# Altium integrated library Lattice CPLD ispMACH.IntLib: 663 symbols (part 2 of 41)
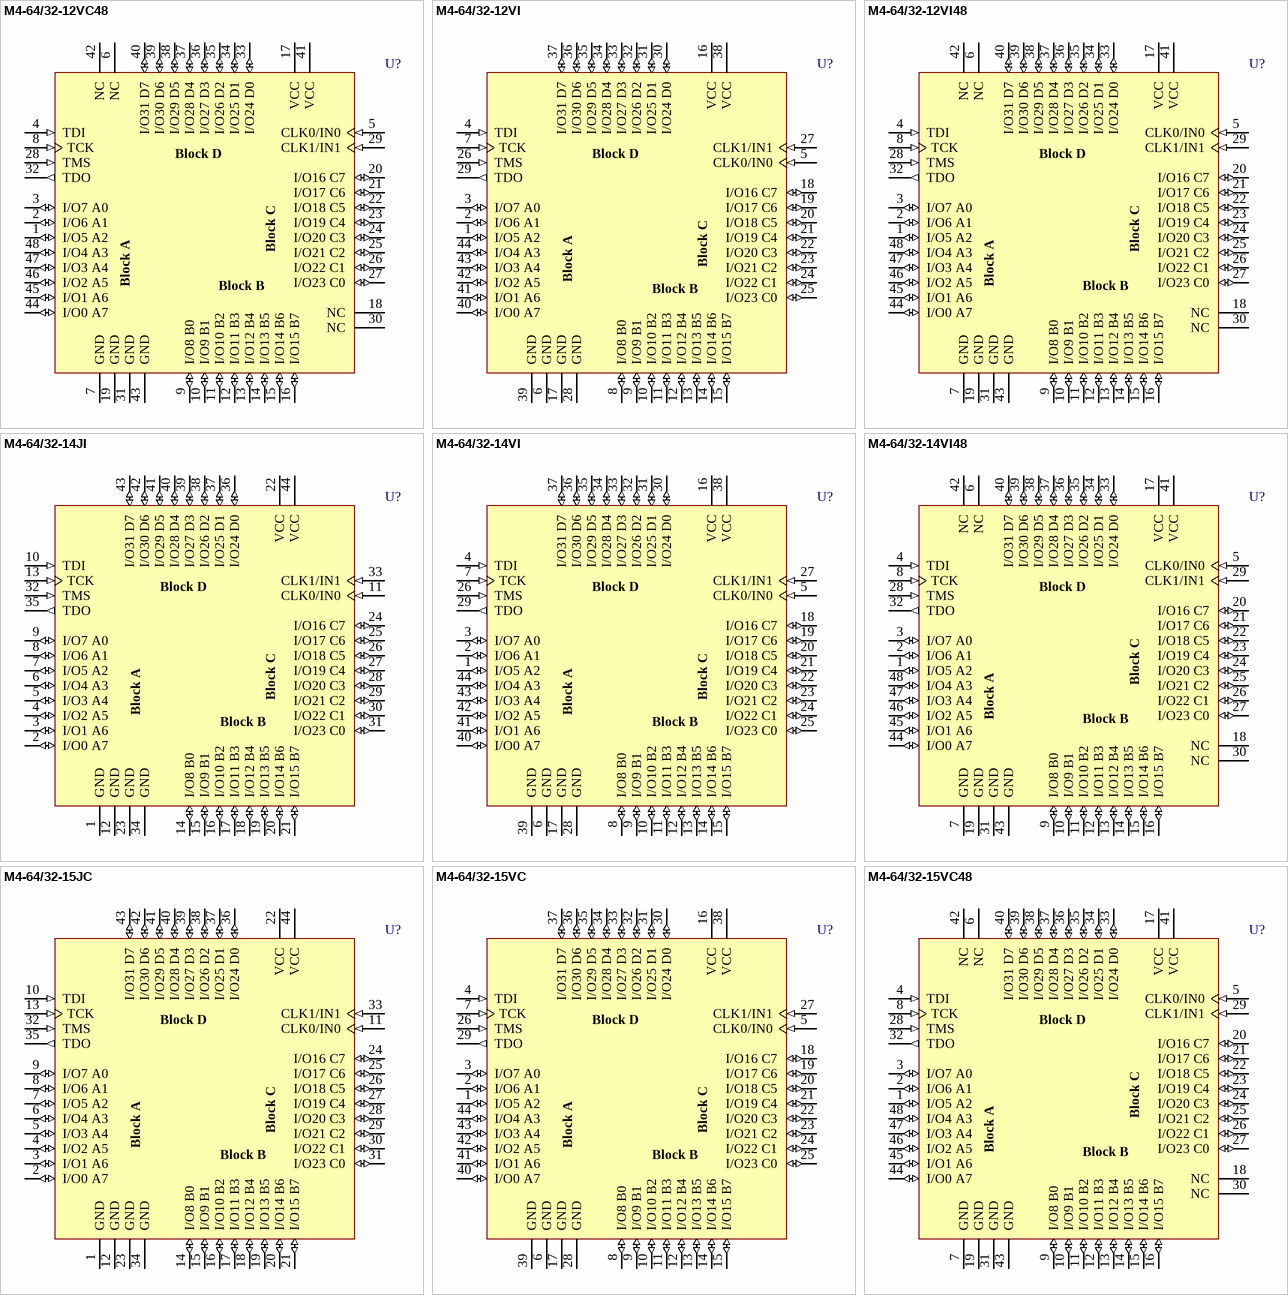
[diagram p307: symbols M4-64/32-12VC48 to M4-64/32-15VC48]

## M4-64/32-14VI48
designator U?
High-Performance EE CMOS In-System Programmable Logic
footprint TQFP48_N (Thin QFP, 48-Leads, Body 7x7mm, Pitch 0.5mm, IPC Medium Density)
footprint TQFP48_L (Thin QFP, 48-Leads, Body 7x7mm, Pitch 0.5mm, IPC High Density)
footprint TQFP48_M (Thin QFP, 48-Leads, Body 7x7mm, Pitch 0.5mm, IPC Low Density)
3D model M4-TQFP48 (48-Pin Thin Quad Flat Pack 0.5 mm Pitch)
pins: 1 I/O5 A2 (io), 2 I/O6 A1 (io), 3 I/O7 A0 (io), 4 TDI (in), 5 CLK0/IN0 (in), 6 NC, 7 GND (power), 8 TCK (in), 9 I/O8 B0 (io), 10 I/O9 B1 (io), 11 I/O10 B2 (io), 12 I/O11 B3 (io), 13 I/O12 B4 (io), 14 I/O13 B5 (io), 15 I/O14 B6 (io), 16 I/O15 B7 (io), 17 VCC (power), 18 NC, 19 GND (power), 20 I/O16 C7 (io), 21 I/O17 C6 (io), 22 I/O18 C5 (io), 23 I/O19 C4 (io), 24 I/O20 C3 (io), 25 I/O21 C2 (io), 26 I/O22 C1 (io), 27 I/O23 C0 (io), 28 TMS (in), 29 CLK1/IN1 (in), 30 NC, 31 GND (power), 32 TDO (out), 33 I/O24 D0 (io), 34 I/O25 D1 (io), 35 I/O26 D2 (io), 36 I/O27 D3 (io), 37 I/O28 D4 (io), 38 I/O29 D5 (io), 39 I/O30 D6 (io), 40 I/O31 D7 (io), 41 VCC (power), 42 NC, 43 GND (power), 44 I/O0 A7 (io), 45 I/O1 A6 (io), 46 I/O2 A5 (io), 47 I/O3 A4 (io), 48 I/O4 A3 (io)

## M4-64/32-15JC
designator U?
High-Performance EE CMOS In-System Programmable Logic
footprint PLCC44_N (Leaded Chip Carrier, 44-Leads, Body 16.6x16.6mm, Pitch 1.27mm, IPC Medium Density)
footprint PLCC44_L (Leaded Chip Carrier, 44-Leads, Body 16.6x16.6mm, Pitch 1.27mm, IPC High Density)
footprint PLCC44_M (Leaded Chip Carrier, 44-Leads, Body 16.6x16.6mm, Pitch 1.27mm, IPC Low Density)
3D model M4-PLCC44 (44-Pin Leaded Chip Carrier 1.27 mm Pitch)
pins: 1 GND (power), 2 I/O0 A7 (io), 3 I/O1 A6 (io), 4 I/O2 A5 (io), 5 I/O3 A4 (io), 6 I/O4 A3 (io), 7 I/O5 A2 (io), 8 I/O6 A1 (io), 9 I/O7 A0 (io), 10 TDI (in), 11 CLK0/IN0 (in), 12 GND (power), 13 TCK (in), 14 I/O8 B0 (io), 15 I/O9 B1 (io), 16 I/O10 B2 (io), 17 I/O11 B3 (io), 18 I/O12 B4 (io), 19 I/O13 B5 (io), 20 I/O14 B6 (io), 21 I/O15 B7 (io), 22 VCC (power), 23 GND (power), 24 I/O16 C7 (io), 25 I/O17 C6 (io), 26 I/O18 C5 (io), 27 I/O19 C4 (io), 28 I/O20 C3 (io), 29 I/O21 C2 (io), 30 I/O22 C1 (io), 31 I/O23 C0 (io), 32 TMS (in), 33 CLK1/IN1 (in), 34 GND (power), 35 TDO (out), 36 I/O24 D0 (io), 37 I/O25 D1 (io), 38 I/O26 D2 (io), 39 I/O27 D3 (io), 40 I/O28 D4 (io), 41 I/O29 D5 (io), 42 I/O30 D6 (io), 43 I/O31 D7 (io), 44 VCC (power)

## M4-64/32-15VC
designator U?
High-Performance EE CMOS In-System Programmable Logic
footprint TQFP44_N (Thin QFP, 44-Leads, Body 10x10mm, Pitch 0.8mm, IPC Medium Density)
footprint TQFP44_L (Thin QFP, 44-Leads, Body 10x10mm, Pitch 0.8mm, IPC High Density)
footprint TQFP44_M (Thin QFP, 44-Leads, Body 10x10mm, Pitch 0.8mm, IPC Low Density)
3D model M4-TQFP44 (44-Pin Thin Quad Flat Pack 0.8 mm Pitch)
pins: 1 I/O5 A2 (io), 2 I/O6 A1 (io), 3 I/O7 A0 (io), 4 TDI (in), 5 CLK0/IN0 (in), 6 GND (power), 7 TCK (in), 8 I/O8 B0 (io), 9 I/O9 B1 (io), 10 I/O10 B2 (io), 11 I/O11 B3 (io), 12 I/O12 B4 (io), 13 I/O13 B5 (io), 14 I/O14 B6 (io), 15 I/O15 B7 (io), 16 VCC (power), 17 GND (power), 18 I/O16 C7 (io), 19 I/O17 C6 (io), 20 I/O18 C5 (io), 21 I/O19 C4 (io), 22 I/O20 C3 (io), 23 I/O21 C2 (io), 24 I/O22 C1 (io), 25 I/O23 C0 (io), 26 TMS (in), 27 CLK1/IN1 (in), 28 GND (power), 29 TDO (out), 30 I/O24 D0 (io), 31 I/O25 D1 (io), 32 I/O26 D2 (io), 33 I/O27 D3 (io), 34 I/O28 D4 (io), 35 I/O29 D5 (io), 36 I/O30 D6 (io), 37 I/O31 D7 (io), 38 VCC (power), 39 GND (power), 40 I/O0 A7 (io), 41 I/O1 A6 (io), 42 I/O2 A5 (io), 43 I/O3 A4 (io), 44 I/O4 A3 (io)

## M4-64/32-15VC48
designator U?
High-Performance EE CMOS In-System Programmable Logic
footprint TQFP48_N (Thin QFP, 48-Leads, Body 7x7mm, Pitch 0.5mm, IPC Medium Density)
footprint TQFP48_L (Thin QFP, 48-Leads, Body 7x7mm, Pitch 0.5mm, IPC High Density)
footprint TQFP48_M (Thin QFP, 48-Leads, Body 7x7mm, Pitch 0.5mm, IPC Low Density)
3D model M4-TQFP48 (48-Pin Thin Quad Flat Pack 0.5 mm Pitch)
pins: 1 I/O5 A2 (io), 2 I/O6 A1 (io), 3 I/O7 A0 (io), 4 TDI (in), 5 CLK0/IN0 (in), 6 NC, 7 GND (power), 8 TCK (in), 9 I/O8 B0 (io), 10 I/O9 B1 (io), 11 I/O10 B2 (io), 12 I/O11 B3 (io), 13 I/O12 B4 (io), 14 I/O13 B5 (io), 15 I/O14 B6 (io), 16 I/O15 B7 (io), 17 VCC (power), 18 NC, 19 GND (power), 20 I/O16 C7 (io), 21 I/O17 C6 (io), 22 I/O18 C5 (io), 23 I/O19 C4 (io), 24 I/O20 C3 (io), 25 I/O21 C2 (io), 26 I/O22 C1 (io), 27 I/O23 C0 (io), 28 TMS (in), 29 CLK1/IN1 (in), 30 NC, 31 GND (power), 32 TDO (out), 33 I/O24 D0 (io), 34 I/O25 D1 (io), 35 I/O26 D2 (io), 36 I/O27 D3 (io), 37 I/O28 D4 (io), 38 I/O29 D5 (io), 39 I/O30 D6 (io), 40 I/O31 D7 (io), 41 VCC (power), 42 NC, 43 GND (power), 44 I/O0 A7 (io), 45 I/O1 A6 (io), 46 I/O2 A5 (io), 47 I/O3 A4 (io), 48 I/O4 A3 (io)

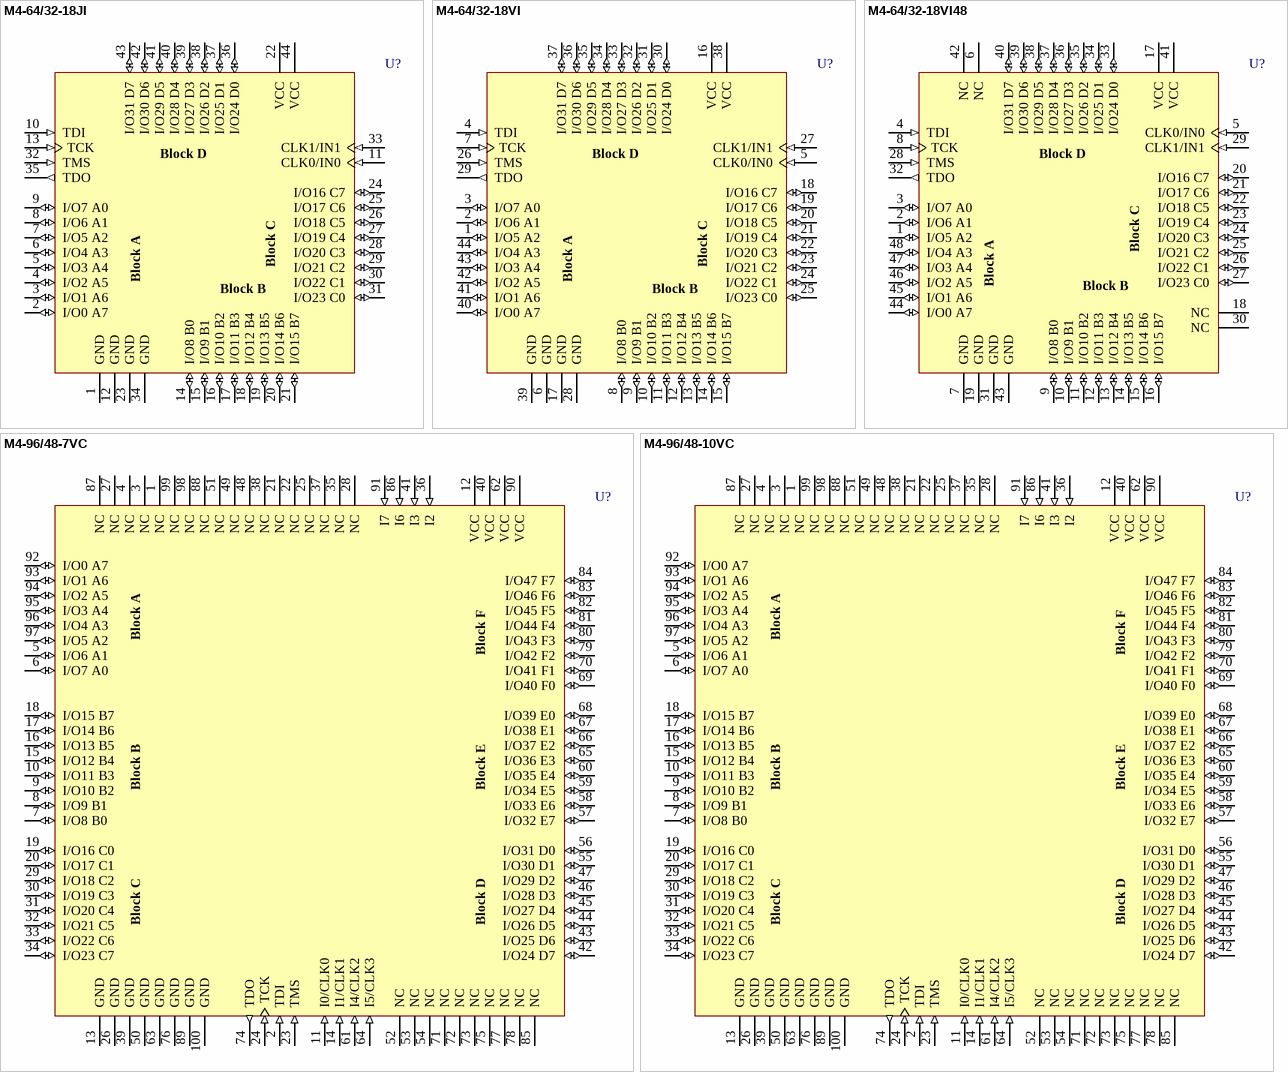
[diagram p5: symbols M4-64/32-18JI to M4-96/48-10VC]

## M4-64/32-18JI
designator U?
High-Performance EE CMOS In-System Programmable Logic
footprint PLCC44_N (Leaded Chip Carrier, 44-Leads, Body 16.6x16.6mm, Pitch 1.27mm, IPC Medium Density)
footprint PLCC44_L (Leaded Chip Carrier, 44-Leads, Body 16.6x16.6mm, Pitch 1.27mm, IPC High Density)
footprint PLCC44_M (Leaded Chip Carrier, 44-Leads, Body 16.6x16.6mm, Pitch 1.27mm, IPC Low Density)
3D model M4-PLCC44 (44-Pin Leaded Chip Carrier 1.27 mm Pitch)
pins: 1 GND (power), 2 I/O0 A7 (io), 3 I/O1 A6 (io), 4 I/O2 A5 (io), 5 I/O3 A4 (io), 6 I/O4 A3 (io), 7 I/O5 A2 (io), 8 I/O6 A1 (io), 9 I/O7 A0 (io), 10 TDI (in), 11 CLK0/IN0 (in), 12 GND (power), 13 TCK (in), 14 I/O8 B0 (io), 15 I/O9 B1 (io), 16 I/O10 B2 (io), 17 I/O11 B3 (io), 18 I/O12 B4 (io), 19 I/O13 B5 (io), 20 I/O14 B6 (io), 21 I/O15 B7 (io), 22 VCC (power), 23 GND (power), 24 I/O16 C7 (io), 25 I/O17 C6 (io), 26 I/O18 C5 (io), 27 I/O19 C4 (io), 28 I/O20 C3 (io), 29 I/O21 C2 (io), 30 I/O22 C1 (io), 31 I/O23 C0 (io), 32 TMS (in), 33 CLK1/IN1 (in), 34 GND (power), 35 TDO (out), 36 I/O24 D0 (io), 37 I/O25 D1 (io), 38 I/O26 D2 (io), 39 I/O27 D3 (io), 40 I/O28 D4 (io), 41 I/O29 D5 (io), 42 I/O30 D6 (io), 43 I/O31 D7 (io), 44 VCC (power)

## M4-64/32-18VI
designator U?
High-Performance EE CMOS In-System Programmable Logic
footprint TQFP44_N (Thin QFP, 44-Leads, Body 10x10mm, Pitch 0.8mm, IPC Medium Density)
footprint TQFP44_L (Thin QFP, 44-Leads, Body 10x10mm, Pitch 0.8mm, IPC High Density)
footprint TQFP44_M (Thin QFP, 44-Leads, Body 10x10mm, Pitch 0.8mm, IPC Low Density)
3D model M4-TQFP44 (44-Pin Thin Quad Flat Pack 0.8 mm Pitch)
pins: 1 I/O5 A2 (io), 2 I/O6 A1 (io), 3 I/O7 A0 (io), 4 TDI (in), 5 CLK0/IN0 (in), 6 GND (power), 7 TCK (in), 8 I/O8 B0 (io), 9 I/O9 B1 (io), 10 I/O10 B2 (io), 11 I/O11 B3 (io), 12 I/O12 B4 (io), 13 I/O13 B5 (io), 14 I/O14 B6 (io), 15 I/O15 B7 (io), 16 VCC (power), 17 GND (power), 18 I/O16 C7 (io), 19 I/O17 C6 (io), 20 I/O18 C5 (io), 21 I/O19 C4 (io), 22 I/O20 C3 (io), 23 I/O21 C2 (io), 24 I/O22 C1 (io), 25 I/O23 C0 (io), 26 TMS (in), 27 CLK1/IN1 (in), 28 GND (power), 29 TDO (out), 30 I/O24 D0 (io), 31 I/O25 D1 (io), 32 I/O26 D2 (io), 33 I/O27 D3 (io), 34 I/O28 D4 (io), 35 I/O29 D5 (io), 36 I/O30 D6 (io), 37 I/O31 D7 (io), 38 VCC (power), 39 GND (power), 40 I/O0 A7 (io), 41 I/O1 A6 (io), 42 I/O2 A5 (io), 43 I/O3 A4 (io), 44 I/O4 A3 (io)

## M4-64/32-18VI48
designator U?
High-Performance EE CMOS In-System Programmable Logic
footprint TQFP48_N (Thin QFP, 48-Leads, Body 7x7mm, Pitch 0.5mm, IPC Medium Density)
footprint TQFP48_L (Thin QFP, 48-Leads, Body 7x7mm, Pitch 0.5mm, IPC High Density)
footprint TQFP48_M (Thin QFP, 48-Leads, Body 7x7mm, Pitch 0.5mm, IPC Low Density)
3D model M4-TQFP48 (48-Pin Thin Quad Flat Pack 0.5 mm Pitch)
pins: 1 I/O5 A2 (io), 2 I/O6 A1 (io), 3 I/O7 A0 (io), 4 TDI (in), 5 CLK0/IN0 (in), 6 NC, 7 GND (power), 8 TCK (in), 9 I/O8 B0 (io), 10 I/O9 B1 (io), 11 I/O10 B2 (io), 12 I/O11 B3 (io), 13 I/O12 B4 (io), 14 I/O13 B5 (io), 15 I/O14 B6 (io), 16 I/O15 B7 (io), 17 VCC (power), 18 NC, 19 GND (power), 20 I/O16 C7 (io), 21 I/O17 C6 (io), 22 I/O18 C5 (io), 23 I/O19 C4 (io), 24 I/O20 C3 (io), 25 I/O21 C2 (io), 26 I/O22 C1 (io), 27 I/O23 C0 (io), 28 TMS (in), 29 CLK1/IN1 (in), 30 NC, 31 GND (power), 32 TDO (out), 33 I/O24 D0 (io), 34 I/O25 D1 (io), 35 I/O26 D2 (io), 36 I/O27 D3 (io), 37 I/O28 D4 (io), 38 I/O29 D5 (io), 39 I/O30 D6 (io), 40 I/O31 D7 (io), 41 VCC (power), 42 NC, 43 GND (power), 44 I/O0 A7 (io), 45 I/O1 A6 (io), 46 I/O2 A5 (io), 47 I/O3 A4 (io), 48 I/O4 A3 (io)

## M4-96/48-7VC
designator U?
High-Performance EE CMOS In-System Programmable Logic
footprint TQFP100_N (Thin QFP, 100-Leads, Body 14x14mm, Pitch 0.5mm, IPC Medium Density)
footprint TQFP100_L (Thin QFP, 100-Leads, Body 14x14mm, Pitch 0.5mm, IPC High Density)
footprint TQFP100_M (Thin QFP, 100-Leads, Body 14x14mm, Pitch 0.5mm, IPC Low Density)
3D model M4-TQFP100 (100-Pin Thin Quad Flat Pack (TQFP100))
pins: 1 NC, 2 TDI (in), 3 NC, 4 NC, 5 I/O6 A1 (io), 6 I/O7 A0 (io), 7 I/O8 B0 (io), 8 I/O9 B1 (io), 9 I/O10 B2 (io), 10 I/O11 B3 (io), 11 I0/CLK0 (in), 12 VCC (power), 13 GND (power), 14 I1/CLK1 (in), 15 I/O12 B4 (io), 16 I/O13 B5 (io), 17 I/O14 B6 (io), 18 I/O15 B7 (io), 19 I/O16 C0 (io), 20 I/O17 C1 (io), 21 NC, 22 NC, 23 TMS (in), 24 TCK (in), 25 NC, 26 GND (power), 27 NC, 28 NC, 29 I/O18 C2 (io), 30 I/O19 C3 (io), 31 I/O20 C4 (io), 32 I/O21 C5 (io), 33 I/O22 C6 (io), 34 I/O23 C7 (io), 35 NC, 36 I2 (in), 37 NC, 38 NC, 39 GND (power), 40 VCC (power), 41 I3 (in), 42 I/O24 D7 (io), 43 I/O25 D6 (io), 44 I/O26 D5 (io), 45 I/O27 D4 (io), 46 I/O28 D3 (io), 47 I/O29 D2 (io), 48 NC, 49 NC, 50 GND (power), 51 NC, 52 NC, 53 NC, 54 NC, 55 I/O30 D1 (io), 56 I/O31 D0 (io), 57 I/O32 E7 (io), 58 I/O33 E6 (io), 59 I/O34 E5 (io), 60 I/O35 E4 (io), 61 I4/CLK2 (in), 62 VCC (power), 63 GND (power), 64 I5/CLK3 (in), 65 I/O36 E3 (io), 66 I/O37 E2 (io), 67 I/O38 E1 (io), 68 I/O39 E0 (io), 69 I/O40 F0 (io), 70 I/O41 F1 (io), 71 NC, 72 NC, 73 NC, 74 TDO (out), 75 NC, 76 GND (power), 77 NC, 78 NC, 79 I/O42 F2 (io), 80 I/O43 F3 (io), 81 I/O44 F4 (io), 82 I/O45 F5 (io), 83 I/O46 F6 (io), 84 I/O47 F7 (io), 85 NC, 86 I6 (in), 87 NC, 88 NC, 89 GND (power), 90 VCC (power), 91 I7 (in), 92 I/O0 A7 (io), 93 I/O1 A6 (io), 94 I/O2 A5 (io), 95 I/O3 A4 (io), 96 I/O4 A3 (io), 97 I/O5 A2 (io), 98 NC, 99 NC, 100 GND (power)

## M4-96/48-10VC
designator U?
High-Performance EE CMOS In-System Programmable Logic
footprint TQFP100_N (Thin QFP, 100-Leads, Body 14x14mm, Pitch 0.5mm, IPC Medium Density)
footprint TQFP100_L (Thin QFP, 100-Leads, Body 14x14mm, Pitch 0.5mm, IPC High Density)
footprint TQFP100_M (Thin QFP, 100-Leads, Body 14x14mm, Pitch 0.5mm, IPC Low Density)
3D model M4-TQFP100 (100-Pin Thin Quad Flat Pack (TQFP100))
pins: 1 NC, 2 TDI (in), 3 NC, 4 NC, 5 I/O6 A1 (io), 6 I/O7 A0 (io), 7 I/O8 B0 (io), 8 I/O9 B1 (io), 9 I/O10 B2 (io), 10 I/O11 B3 (io), 11 I0/CLK0 (in), 12 VCC (power), 13 GND (power), 14 I1/CLK1 (in), 15 I/O12 B4 (io), 16 I/O13 B5 (io), 17 I/O14 B6 (io), 18 I/O15 B7 (io), 19 I/O16 C0 (io), 20 I/O17 C1 (io), 21 NC, 22 NC, 23 TMS (in), 24 TCK (in), 25 NC, 26 GND (power), 27 NC, 28 NC, 29 I/O18 C2 (io), 30 I/O19 C3 (io), 31 I/O20 C4 (io), 32 I/O21 C5 (io), 33 I/O22 C6 (io), 34 I/O23 C7 (io), 35 NC, 36 I2 (in), 37 NC, 38 NC, 39 GND (power), 40 VCC (power), 41 I3 (in), 42 I/O24 D7 (io), 43 I/O25 D6 (io), 44 I/O26 D5 (io), 45 I/O27 D4 (io), 46 I/O28 D3 (io), 47 I/O29 D2 (io), 48 NC, 49 NC, 50 GND (power), 51 NC, 52 NC, 53 NC, 54 NC, 55 I/O30 D1 (io), 56 I/O31 D0 (io), 57 I/O32 E7 (io), 58 I/O33 E6 (io), 59 I/O34 E5 (io), 60 I/O35 E4 (io), 61 I4/CLK2 (in), 62 VCC (power), 63 GND (power), 64 I5/CLK3 (in), 65 I/O36 E3 (io), 66 I/O37 E2 (io), 67 I/O38 E1 (io), 68 I/O39 E0 (io), 69 I/O40 F0 (io), 70 I/O41 F1 (io), 71 NC, 72 NC, 73 NC, 74 TDO (out), 75 NC, 76 GND (power), 77 NC, 78 NC, 79 I/O42 F2 (io), 80 I/O43 F3 (io), 81 I/O44 F4 (io), 82 I/O45 F5 (io), 83 I/O46 F6 (io), 84 I/O47 F7 (io), 85 NC, 86 I6 (in), 87 NC, 88 NC, 89 GND (power), 90 VCC (power), 91 I7 (in), 92 I/O0 A7 (io), 93 I/O1 A6 (io), 94 I/O2 A5 (io), 95 I/O3 A4 (io), 96 I/O4 A3 (io), 97 I/O5 A2 (io), 98 NC, 99 NC, 100 GND (power)

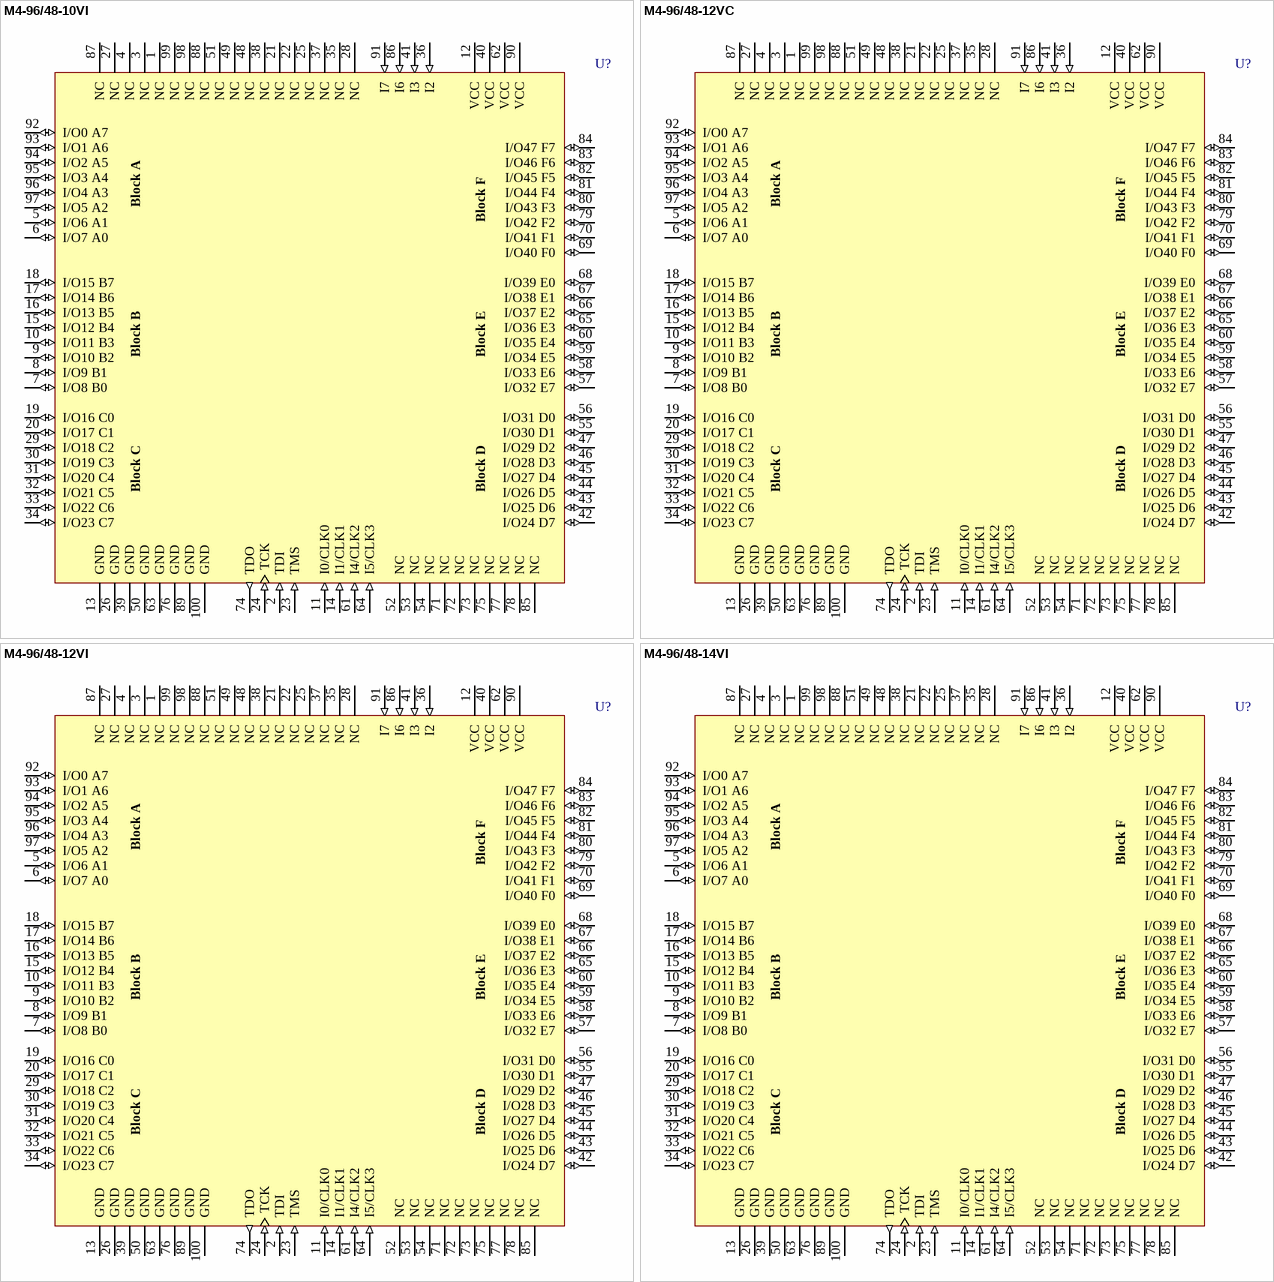
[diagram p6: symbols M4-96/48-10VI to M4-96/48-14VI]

## M4-96/48-10VI
designator U?
High-Performance EE CMOS In-System Programmable Logic
footprint TQFP100_N (Thin QFP, 100-Leads, Body 14x14mm, Pitch 0.5mm, IPC Medium Density)
footprint TQFP100_L (Thin QFP, 100-Leads, Body 14x14mm, Pitch 0.5mm, IPC High Density)
footprint TQFP100_M (Thin QFP, 100-Leads, Body 14x14mm, Pitch 0.5mm, IPC Low Density)
3D model M4-TQFP100 (100-Pin Thin Quad Flat Pack (TQFP100))
pins: 1 NC, 2 TDI (in), 3 NC, 4 NC, 5 I/O6 A1 (io), 6 I/O7 A0 (io), 7 I/O8 B0 (io), 8 I/O9 B1 (io), 9 I/O10 B2 (io), 10 I/O11 B3 (io), 11 I0/CLK0 (in), 12 VCC (power), 13 GND (power), 14 I1/CLK1 (in), 15 I/O12 B4 (io), 16 I/O13 B5 (io), 17 I/O14 B6 (io), 18 I/O15 B7 (io), 19 I/O16 C0 (io), 20 I/O17 C1 (io), 21 NC, 22 NC, 23 TMS (in), 24 TCK (in), 25 NC, 26 GND (power), 27 NC, 28 NC, 29 I/O18 C2 (io), 30 I/O19 C3 (io), 31 I/O20 C4 (io), 32 I/O21 C5 (io), 33 I/O22 C6 (io), 34 I/O23 C7 (io), 35 NC, 36 I2 (in), 37 NC, 38 NC, 39 GND (power), 40 VCC (power), 41 I3 (in), 42 I/O24 D7 (io), 43 I/O25 D6 (io), 44 I/O26 D5 (io), 45 I/O27 D4 (io), 46 I/O28 D3 (io), 47 I/O29 D2 (io), 48 NC, 49 NC, 50 GND (power), 51 NC, 52 NC, 53 NC, 54 NC, 55 I/O30 D1 (io), 56 I/O31 D0 (io), 57 I/O32 E7 (io), 58 I/O33 E6 (io), 59 I/O34 E5 (io), 60 I/O35 E4 (io), 61 I4/CLK2 (in), 62 VCC (power), 63 GND (power), 64 I5/CLK3 (in), 65 I/O36 E3 (io), 66 I/O37 E2 (io), 67 I/O38 E1 (io), 68 I/O39 E0 (io), 69 I/O40 F0 (io), 70 I/O41 F1 (io), 71 NC, 72 NC, 73 NC, 74 TDO (out), 75 NC, 76 GND (power), 77 NC, 78 NC, 79 I/O42 F2 (io), 80 I/O43 F3 (io), 81 I/O44 F4 (io), 82 I/O45 F5 (io), 83 I/O46 F6 (io), 84 I/O47 F7 (io), 85 NC, 86 I6 (in), 87 NC, 88 NC, 89 GND (power), 90 VCC (power), 91 I7 (in), 92 I/O0 A7 (io), 93 I/O1 A6 (io), 94 I/O2 A5 (io), 95 I/O3 A4 (io), 96 I/O4 A3 (io), 97 I/O5 A2 (io), 98 NC, 99 NC, 100 GND (power)

## M4-96/48-12VC
designator U?
High-Performance EE CMOS In-System Programmable Logic
footprint TQFP100_N (Thin QFP, 100-Leads, Body 14x14mm, Pitch 0.5mm, IPC Medium Density)
footprint TQFP100_L (Thin QFP, 100-Leads, Body 14x14mm, Pitch 0.5mm, IPC High Density)
footprint TQFP100_M (Thin QFP, 100-Leads, Body 14x14mm, Pitch 0.5mm, IPC Low Density)
3D model M4-TQFP100 (100-Pin Thin Quad Flat Pack (TQFP100))
pins: 1 NC, 2 TDI (in), 3 NC, 4 NC, 5 I/O6 A1 (io), 6 I/O7 A0 (io), 7 I/O8 B0 (io), 8 I/O9 B1 (io), 9 I/O10 B2 (io), 10 I/O11 B3 (io), 11 I0/CLK0 (in), 12 VCC (power), 13 GND (power), 14 I1/CLK1 (in), 15 I/O12 B4 (io), 16 I/O13 B5 (io), 17 I/O14 B6 (io), 18 I/O15 B7 (io), 19 I/O16 C0 (io), 20 I/O17 C1 (io), 21 NC, 22 NC, 23 TMS (in), 24 TCK (in), 25 NC, 26 GND (power), 27 NC, 28 NC, 29 I/O18 C2 (io), 30 I/O19 C3 (io), 31 I/O20 C4 (io), 32 I/O21 C5 (io), 33 I/O22 C6 (io), 34 I/O23 C7 (io), 35 NC, 36 I2 (in), 37 NC, 38 NC, 39 GND (power), 40 VCC (power), 41 I3 (in), 42 I/O24 D7 (io), 43 I/O25 D6 (io), 44 I/O26 D5 (io), 45 I/O27 D4 (io), 46 I/O28 D3 (io), 47 I/O29 D2 (io), 48 NC, 49 NC, 50 GND (power), 51 NC, 52 NC, 53 NC, 54 NC, 55 I/O30 D1 (io), 56 I/O31 D0 (io), 57 I/O32 E7 (io), 58 I/O33 E6 (io), 59 I/O34 E5 (io), 60 I/O35 E4 (io), 61 I4/CLK2 (in), 62 VCC (power), 63 GND (power), 64 I5/CLK3 (in), 65 I/O36 E3 (io), 66 I/O37 E2 (io), 67 I/O38 E1 (io), 68 I/O39 E0 (io), 69 I/O40 F0 (io), 70 I/O41 F1 (io), 71 NC, 72 NC, 73 NC, 74 TDO (out), 75 NC, 76 GND (power), 77 NC, 78 NC, 79 I/O42 F2 (io), 80 I/O43 F3 (io), 81 I/O44 F4 (io), 82 I/O45 F5 (io), 83 I/O46 F6 (io), 84 I/O47 F7 (io), 85 NC, 86 I6 (in), 87 NC, 88 NC, 89 GND (power), 90 VCC (power), 91 I7 (in), 92 I/O0 A7 (io), 93 I/O1 A6 (io), 94 I/O2 A5 (io), 95 I/O3 A4 (io), 96 I/O4 A3 (io), 97 I/O5 A2 (io), 98 NC, 99 NC, 100 GND (power)

## M4-96/48-12VI
designator U?
High-Performance EE CMOS In-System Programmable Logic
footprint TQFP100_N (Thin QFP, 100-Leads, Body 14x14mm, Pitch 0.5mm, IPC Medium Density)
footprint TQFP100_L (Thin QFP, 100-Leads, Body 14x14mm, Pitch 0.5mm, IPC High Density)
footprint TQFP100_M (Thin QFP, 100-Leads, Body 14x14mm, Pitch 0.5mm, IPC Low Density)
3D model M4-TQFP100 (100-Pin Thin Quad Flat Pack (TQFP100))
pins: 1 NC, 2 TDI (in), 3 NC, 4 NC, 5 I/O6 A1 (io), 6 I/O7 A0 (io), 7 I/O8 B0 (io), 8 I/O9 B1 (io), 9 I/O10 B2 (io), 10 I/O11 B3 (io), 11 I0/CLK0 (in), 12 VCC (power), 13 GND (power), 14 I1/CLK1 (in), 15 I/O12 B4 (io), 16 I/O13 B5 (io), 17 I/O14 B6 (io), 18 I/O15 B7 (io), 19 I/O16 C0 (io), 20 I/O17 C1 (io), 21 NC, 22 NC, 23 TMS (in), 24 TCK (in), 25 NC, 26 GND (power), 27 NC, 28 NC, 29 I/O18 C2 (io), 30 I/O19 C3 (io), 31 I/O20 C4 (io), 32 I/O21 C5 (io), 33 I/O22 C6 (io), 34 I/O23 C7 (io), 35 NC, 36 I2 (in), 37 NC, 38 NC, 39 GND (power), 40 VCC (power), 41 I3 (in), 42 I/O24 D7 (io), 43 I/O25 D6 (io), 44 I/O26 D5 (io), 45 I/O27 D4 (io), 46 I/O28 D3 (io), 47 I/O29 D2 (io), 48 NC, 49 NC, 50 GND (power), 51 NC, 52 NC, 53 NC, 54 NC, 55 I/O30 D1 (io), 56 I/O31 D0 (io), 57 I/O32 E7 (io), 58 I/O33 E6 (io), 59 I/O34 E5 (io), 60 I/O35 E4 (io), 61 I4/CLK2 (in), 62 VCC (power), 63 GND (power), 64 I5/CLK3 (in), 65 I/O36 E3 (io), 66 I/O37 E2 (io), 67 I/O38 E1 (io), 68 I/O39 E0 (io), 69 I/O40 F0 (io), 70 I/O41 F1 (io), 71 NC, 72 NC, 73 NC, 74 TDO (out), 75 NC, 76 GND (power), 77 NC, 78 NC, 79 I/O42 F2 (io), 80 I/O43 F3 (io), 81 I/O44 F4 (io), 82 I/O45 F5 (io), 83 I/O46 F6 (io), 84 I/O47 F7 (io), 85 NC, 86 I6 (in), 87 NC, 88 NC, 89 GND (power), 90 VCC (power), 91 I7 (in), 92 I/O0 A7 (io), 93 I/O1 A6 (io), 94 I/O2 A5 (io), 95 I/O3 A4 (io), 96 I/O4 A3 (io), 97 I/O5 A2 (io), 98 NC, 99 NC, 100 GND (power)

## M4-96/48-14VI
designator U?
High-Performance EE CMOS In-System Programmable Logic
footprint TQFP100_N (Thin QFP, 100-Leads, Body 14x14mm, Pitch 0.5mm, IPC Medium Density)
footprint TQFP100_L (Thin QFP, 100-Leads, Body 14x14mm, Pitch 0.5mm, IPC High Density)
footprint TQFP100_M (Thin QFP, 100-Leads, Body 14x14mm, Pitch 0.5mm, IPC Low Density)
3D model M4-TQFP100 (100-Pin Thin Quad Flat Pack (TQFP100))
pins: 1 NC, 2 TDI (in), 3 NC, 4 NC, 5 I/O6 A1 (io), 6 I/O7 A0 (io), 7 I/O8 B0 (io), 8 I/O9 B1 (io), 9 I/O10 B2 (io), 10 I/O11 B3 (io), 11 I0/CLK0 (in), 12 VCC (power), 13 GND (power), 14 I1/CLK1 (in), 15 I/O12 B4 (io), 16 I/O13 B5 (io), 17 I/O14 B6 (io), 18 I/O15 B7 (io), 19 I/O16 C0 (io), 20 I/O17 C1 (io), 21 NC, 22 NC, 23 TMS (in), 24 TCK (in), 25 NC, 26 GND (power), 27 NC, 28 NC, 29 I/O18 C2 (io), 30 I/O19 C3 (io), 31 I/O20 C4 (io), 32 I/O21 C5 (io), 33 I/O22 C6 (io), 34 I/O23 C7 (io), 35 NC, 36 I2 (in), 37 NC, 38 NC, 39 GND (power), 40 VCC (power), 41 I3 (in), 42 I/O24 D7 (io), 43 I/O25 D6 (io), 44 I/O26 D5 (io), 45 I/O27 D4 (io), 46 I/O28 D3 (io), 47 I/O29 D2 (io), 48 NC, 49 NC, 50 GND (power), 51 NC, 52 NC, 53 NC, 54 NC, 55 I/O30 D1 (io), 56 I/O31 D0 (io), 57 I/O32 E7 (io), 58 I/O33 E6 (io), 59 I/O34 E5 (io), 60 I/O35 E4 (io), 61 I4/CLK2 (in), 62 VCC (power), 63 GND (power), 64 I5/CLK3 (in), 65 I/O36 E3 (io), 66 I/O37 E2 (io), 67 I/O38 E1 (io), 68 I/O39 E0 (io), 69 I/O40 F0 (io), 70 I/O41 F1 (io), 71 NC, 72 NC, 73 NC, 74 TDO (out), 75 NC, 76 GND (power), 77 NC, 78 NC, 79 I/O42 F2 (io), 80 I/O43 F3 (io), 81 I/O44 F4 (io), 82 I/O45 F5 (io), 83 I/O46 F6 (io), 84 I/O47 F7 (io), 85 NC, 86 I6 (in), 87 NC, 88 NC, 89 GND (power), 90 VCC (power), 91 I7 (in), 92 I/O0 A7 (io), 93 I/O1 A6 (io), 94 I/O2 A5 (io), 95 I/O3 A4 (io), 96 I/O4 A3 (io), 97 I/O5 A2 (io), 98 NC, 99 NC, 100 GND (power)

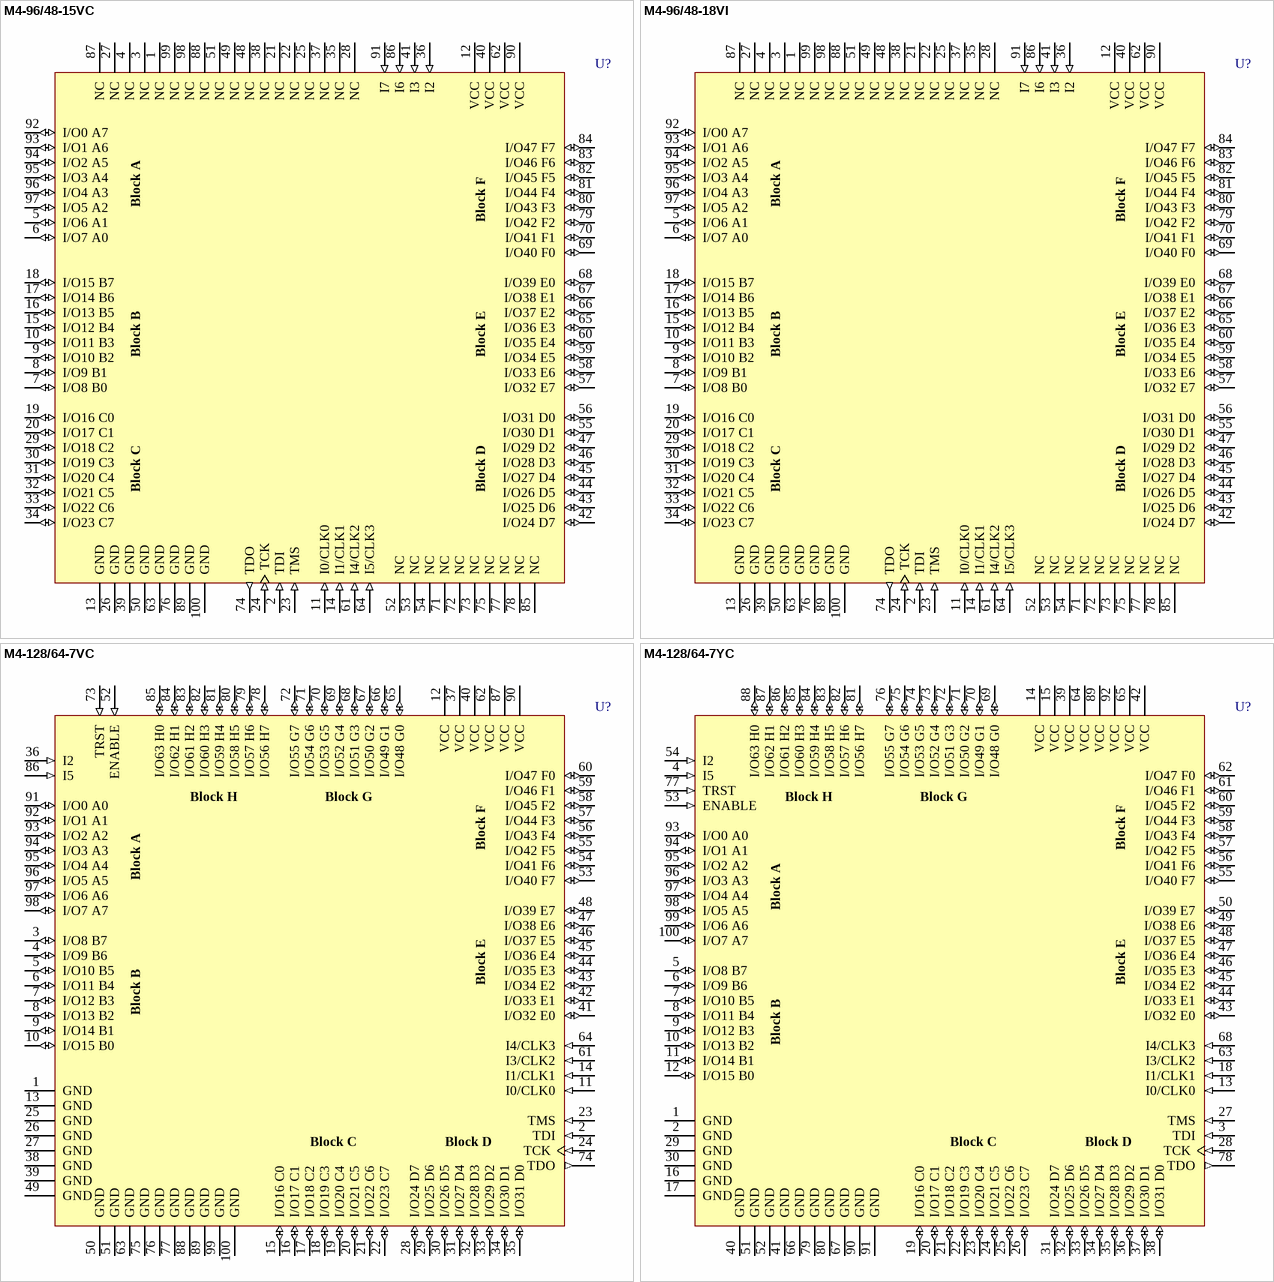
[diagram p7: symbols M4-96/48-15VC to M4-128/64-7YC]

## M4-96/48-15VC
designator U?
High-Performance EE CMOS In-System Programmable Logic
footprint TQFP100_N (Thin QFP, 100-Leads, Body 14x14mm, Pitch 0.5mm, IPC Medium Density)
footprint TQFP100_L (Thin QFP, 100-Leads, Body 14x14mm, Pitch 0.5mm, IPC High Density)
footprint TQFP100_M (Thin QFP, 100-Leads, Body 14x14mm, Pitch 0.5mm, IPC Low Density)
3D model M4-TQFP100 (100-Pin Thin Quad Flat Pack (TQFP100))
pins: 1 NC, 2 TDI (in), 3 NC, 4 NC, 5 I/O6 A1 (io), 6 I/O7 A0 (io), 7 I/O8 B0 (io), 8 I/O9 B1 (io), 9 I/O10 B2 (io), 10 I/O11 B3 (io), 11 I0/CLK0 (in), 12 VCC (power), 13 GND (power), 14 I1/CLK1 (in), 15 I/O12 B4 (io), 16 I/O13 B5 (io), 17 I/O14 B6 (io), 18 I/O15 B7 (io), 19 I/O16 C0 (io), 20 I/O17 C1 (io), 21 NC, 22 NC, 23 TMS (in), 24 TCK (in), 25 NC, 26 GND (power), 27 NC, 28 NC, 29 I/O18 C2 (io), 30 I/O19 C3 (io), 31 I/O20 C4 (io), 32 I/O21 C5 (io), 33 I/O22 C6 (io), 34 I/O23 C7 (io), 35 NC, 36 I2 (in), 37 NC, 38 NC, 39 GND (power), 40 VCC (power), 41 I3 (in), 42 I/O24 D7 (io), 43 I/O25 D6 (io), 44 I/O26 D5 (io), 45 I/O27 D4 (io), 46 I/O28 D3 (io), 47 I/O29 D2 (io), 48 NC, 49 NC, 50 GND (power), 51 NC, 52 NC, 53 NC, 54 NC, 55 I/O30 D1 (io), 56 I/O31 D0 (io), 57 I/O32 E7 (io), 58 I/O33 E6 (io), 59 I/O34 E5 (io), 60 I/O35 E4 (io), 61 I4/CLK2 (in), 62 VCC (power), 63 GND (power), 64 I5/CLK3 (in), 65 I/O36 E3 (io), 66 I/O37 E2 (io), 67 I/O38 E1 (io), 68 I/O39 E0 (io), 69 I/O40 F0 (io), 70 I/O41 F1 (io), 71 NC, 72 NC, 73 NC, 74 TDO (out), 75 NC, 76 GND (power), 77 NC, 78 NC, 79 I/O42 F2 (io), 80 I/O43 F3 (io), 81 I/O44 F4 (io), 82 I/O45 F5 (io), 83 I/O46 F6 (io), 84 I/O47 F7 (io), 85 NC, 86 I6 (in), 87 NC, 88 NC, 89 GND (power), 90 VCC (power), 91 I7 (in), 92 I/O0 A7 (io), 93 I/O1 A6 (io), 94 I/O2 A5 (io), 95 I/O3 A4 (io), 96 I/O4 A3 (io), 97 I/O5 A2 (io), 98 NC, 99 NC, 100 GND (power)

## M4-96/48-18VI
designator U?
High-Performance EE CMOS In-System Programmable Logic
footprint TQFP100_N (Thin QFP, 100-Leads, Body 14x14mm, Pitch 0.5mm, IPC Medium Density)
footprint TQFP100_L (Thin QFP, 100-Leads, Body 14x14mm, Pitch 0.5mm, IPC High Density)
footprint TQFP100_M (Thin QFP, 100-Leads, Body 14x14mm, Pitch 0.5mm, IPC Low Density)
3D model M4-TQFP100 (100-Pin Thin Quad Flat Pack (TQFP100))
pins: 1 NC, 2 TDI (in), 3 NC, 4 NC, 5 I/O6 A1 (io), 6 I/O7 A0 (io), 7 I/O8 B0 (io), 8 I/O9 B1 (io), 9 I/O10 B2 (io), 10 I/O11 B3 (io), 11 I0/CLK0 (in), 12 VCC (power), 13 GND (power), 14 I1/CLK1 (in), 15 I/O12 B4 (io), 16 I/O13 B5 (io), 17 I/O14 B6 (io), 18 I/O15 B7 (io), 19 I/O16 C0 (io), 20 I/O17 C1 (io), 21 NC, 22 NC, 23 TMS (in), 24 TCK (in), 25 NC, 26 GND (power), 27 NC, 28 NC, 29 I/O18 C2 (io), 30 I/O19 C3 (io), 31 I/O20 C4 (io), 32 I/O21 C5 (io), 33 I/O22 C6 (io), 34 I/O23 C7 (io), 35 NC, 36 I2 (in), 37 NC, 38 NC, 39 GND (power), 40 VCC (power), 41 I3 (in), 42 I/O24 D7 (io), 43 I/O25 D6 (io), 44 I/O26 D5 (io), 45 I/O27 D4 (io), 46 I/O28 D3 (io), 47 I/O29 D2 (io), 48 NC, 49 NC, 50 GND (power), 51 NC, 52 NC, 53 NC, 54 NC, 55 I/O30 D1 (io), 56 I/O31 D0 (io), 57 I/O32 E7 (io), 58 I/O33 E6 (io), 59 I/O34 E5 (io), 60 I/O35 E4 (io), 61 I4/CLK2 (in), 62 VCC (power), 63 GND (power), 64 I5/CLK3 (in), 65 I/O36 E3 (io), 66 I/O37 E2 (io), 67 I/O38 E1 (io), 68 I/O39 E0 (io), 69 I/O40 F0 (io), 70 I/O41 F1 (io), 71 NC, 72 NC, 73 NC, 74 TDO (out), 75 NC, 76 GND (power), 77 NC, 78 NC, 79 I/O42 F2 (io), 80 I/O43 F3 (io), 81 I/O44 F4 (io), 82 I/O45 F5 (io), 83 I/O46 F6 (io), 84 I/O47 F7 (io), 85 NC, 86 I6 (in), 87 NC, 88 NC, 89 GND (power), 90 VCC (power), 91 I7 (in), 92 I/O0 A7 (io), 93 I/O1 A6 (io), 94 I/O2 A5 (io), 95 I/O3 A4 (io), 96 I/O4 A3 (io), 97 I/O5 A2 (io), 98 NC, 99 NC, 100 GND (power)

## M4-128/64-7VC
designator U?
High-Performance EE CMOS In-System Programmable Logic
footprint TQFP100_N (Thin QFP, 100-Leads, Body 14x14mm, Pitch 0.5mm, IPC Medium Density)
footprint TQFP100_L (Thin QFP, 100-Leads, Body 14x14mm, Pitch 0.5mm, IPC High Density)
footprint TQFP100_M (Thin QFP, 100-Leads, Body 14x14mm, Pitch 0.5mm, IPC Low Density)
3D model M4-TQFP100 (100-Pin Thin Quad Flat Pack (TQFP100))
pins: 1 GND (power), 2 TDI (in), 3 I/O8 B7 (io), 4 I/O9 B6 (io), 5 I/O10 B5 (io), 6 I/O11 B4 (io), 7 I/O12 B3 (io), 8 I/O13 B2 (io), 9 I/O14 B1 (io), 10 I/O15 B0 (io), 11 I0/CLK0 (in), 12 VCC (power), 13 GND (power), 14 I1/CLK1 (in), 15 I/O16 C0 (io), 16 I/O17 C1 (io), 17 I/O18 C2 (io), 18 I/O19 C3 (io), 19 I/O20 C4 (io), 20 I/O21 C5 (io), 21 I/O22 C6 (io), 22 I/O23 C7 (io), 23 TMS (in), 24 TCK (in), 25 GND (power), 26 GND (power), 27 GND (power), 28 I/O24 D7 (io), 29 I/O25 D6 (io), 30 I/O26 D5 (io), 31 I/O27 D4 (io), 32 I/O28 D3 (io), 33 I/O29 D2 (io), 34 I/O30 D1 (io), 35 I/O31 D0 (io), 36 I2 (in), 37 VCC (power), 38 GND (power), 39 GND (power), 40 VCC (power), 41 I/O32 E0 (io), 42 I/O33 E1 (io), 43 I/O34 E2 (io), 44 I/O35 E3 (io), 45 I/O36 E4 (io), 46 I/O37 E5 (io), 47 I/O38 E6 (io), 48 I/O39 E7 (io), 49 GND (power), 50 GND (power), 51 GND (power), 52 ENABLE (in), 53 I/O40 F7 (io), 54 I/O41 F6 (io), 55 I/O42 F5 (io), 56 I/O43 F4 (io), 57 I/O44 F3 (io), 58 I/O45 F2 (io), 59 I/O46 F1 (io), 60 I/O47 F0 (io), 61 I3/CLK2 (in), 62 VCC (power), 63 GND (power), 64 I4/CLK3 (in), 65 I/O48 G0 (io), 66 I/O49 G1 (io), 67 I/O50 G2 (io), 68 I/O51 G3 (io), 69 I/O52 G4 (io), 70 I/O53 G5 (io), 71 I/O54 G6 (io), 72 I/O55 G7 (io), 73 TRST (in), 74 TDO (out), 75 GND (power), 76 GND (power), 77 GND (power), 78 I/O56 H7 (io), 79 I/O57 H6 (io), 80 I/O58 H5 (io), 81 I/O59 H4 (io), 82 I/O60 H3 (io), 83 I/O61 H2 (io), 84 I/O62 H1 (io), 85 I/O63 H0 (io), 86 I5 (in), 87 VCC (power), 88 GND (power), 89 GND (power), 90 VCC (power), 91 I/O0 A0 (io), 92 I/O1 A1 (io), 93 I/O2 A2 (io), 94 I/O3 A3 (io), 95 I/O4 A4 (io), 96 I/O5 A5 (io), 97 I/O6 A6 (io), 98 I/O7 A7 (io), 99 GND (power), 100 GND (power)

## M4-128/64-7YC
designator U?
High-Performance EE CMOS In-System Programmable Logic
footprint PQFP100_N (QFP, 100-Leads, Body 20x14mm, Pitch 0.65mm, IPC Medium Density)
footprint PQFP100_L (QFP, 100-Leads, Body 20x14mm, Pitch 0.65mm, IPC High Density)
footprint PQFP100_M (QFP, 100-Leads, Body 20x14mm, Pitch 0.65mm, IPC Low Density)
3D model PQFP-100 (100-Pin Quad Flat Pack Rectangular 0.65 mm Pitch)
pins: 1 GND (power), 2 GND (power), 3 TDI (in), 4 I5 (in), 5 I/O8 B7 (io), 6 I/O9 B6 (io), 7 I/O10 B5 (io), 8 I/O11 B4 (io), 9 I/O12 B3 (io), 10 I/O13 B2 (io), 11 I/O14 B1 (io), 12 I/O15 B0 (io), 13 I0/CLK0 (in), 14 VCC (power), 15 VCC (power), 16 GND (power), 17 GND (power), 18 I1/CLK1 (in), 19 I/O16 C0 (io), 20 I/O17 C1 (io), 21 I/O18 C2 (io), 22 I/O19 C3 (io), 23 I/O20 C4 (io), 24 I/O21 C5 (io), 25 I/O22 C6 (io), 26 I/O23 C7 (io), 27 TMS (in), 28 TCK (in), 29 GND (power), 30 GND (power), 31 I/O24 D7 (io), 32 I/O25 D6 (io), 33 I/O26 D5 (io), 34 I/O27 D4 (io), 35 I/O28 D3 (io), 36 I/O29 D2 (io), 37 I/O30 D1 (io), 38 I/O31 D0 (io), 39 VCC (power), 40 GND (power), 41 GND (power), 42 VCC (power), 43 I/O32 E0 (io), 44 I/O33 E1 (io), 45 I/O34 E2 (io), 46 I/O35 E3 (io), 47 I/O36 E4 (io), 48 I/O37 E5 (io), 49 I/O38 E6 (io), 50 I/O39 E7 (io), 51 GND (power), 52 GND (power), 53 ENABLE (in), 54 I2 (in), 55 I/O40 F7 (io), 56 I/O41 F6 (io), 57 I/O42 F5 (io), 58 I/O43 F4 (io), 59 I/O44 F3 (io), 60 I/O45 F2 (io), 61 I/O46 F1 (io), 62 I/O47 F0 (io), 63 I3/CLK2 (in), 64 VCC (power), 65 VCC (power), 66 GND (power), 67 GND (power), 68 I4/CLK3 (in), 69 I/O48 G0 (io), 70 I/O49 G1 (io), 71 I/O50 G2 (io), 72 I/O51 G3 (io), 73 I/O52 G4 (io), 74 I/O53 G5 (io), 75 I/O54 G6 (io), 76 I/O55 G7 (io), 77 TRST (in), 78 TDO (out), 79 GND (power), 80 GND (power), 81 I/O56 H7 (io), 82 I/O57 H6 (io), 83 I/O58 H5 (io), 84 I/O59 H4 (io), 85 I/O60 H3 (io), 86 I/O61 H2 (io), 87 I/O62 H1 (io), 88 I/O63 H0 (io), 89 VCC (power), 90 GND (power), 91 GND (power), 92 VCC (power), 93 I/O0 A0 (io), 94 I/O1 A1 (io), 95 I/O2 A2 (io), 96 I/O3 A3 (io), 97 I/O4 A4 (io), 98 I/O5 A5 (io), 99 I/O6 A6 (io), 100 I/O7 A7 (io)

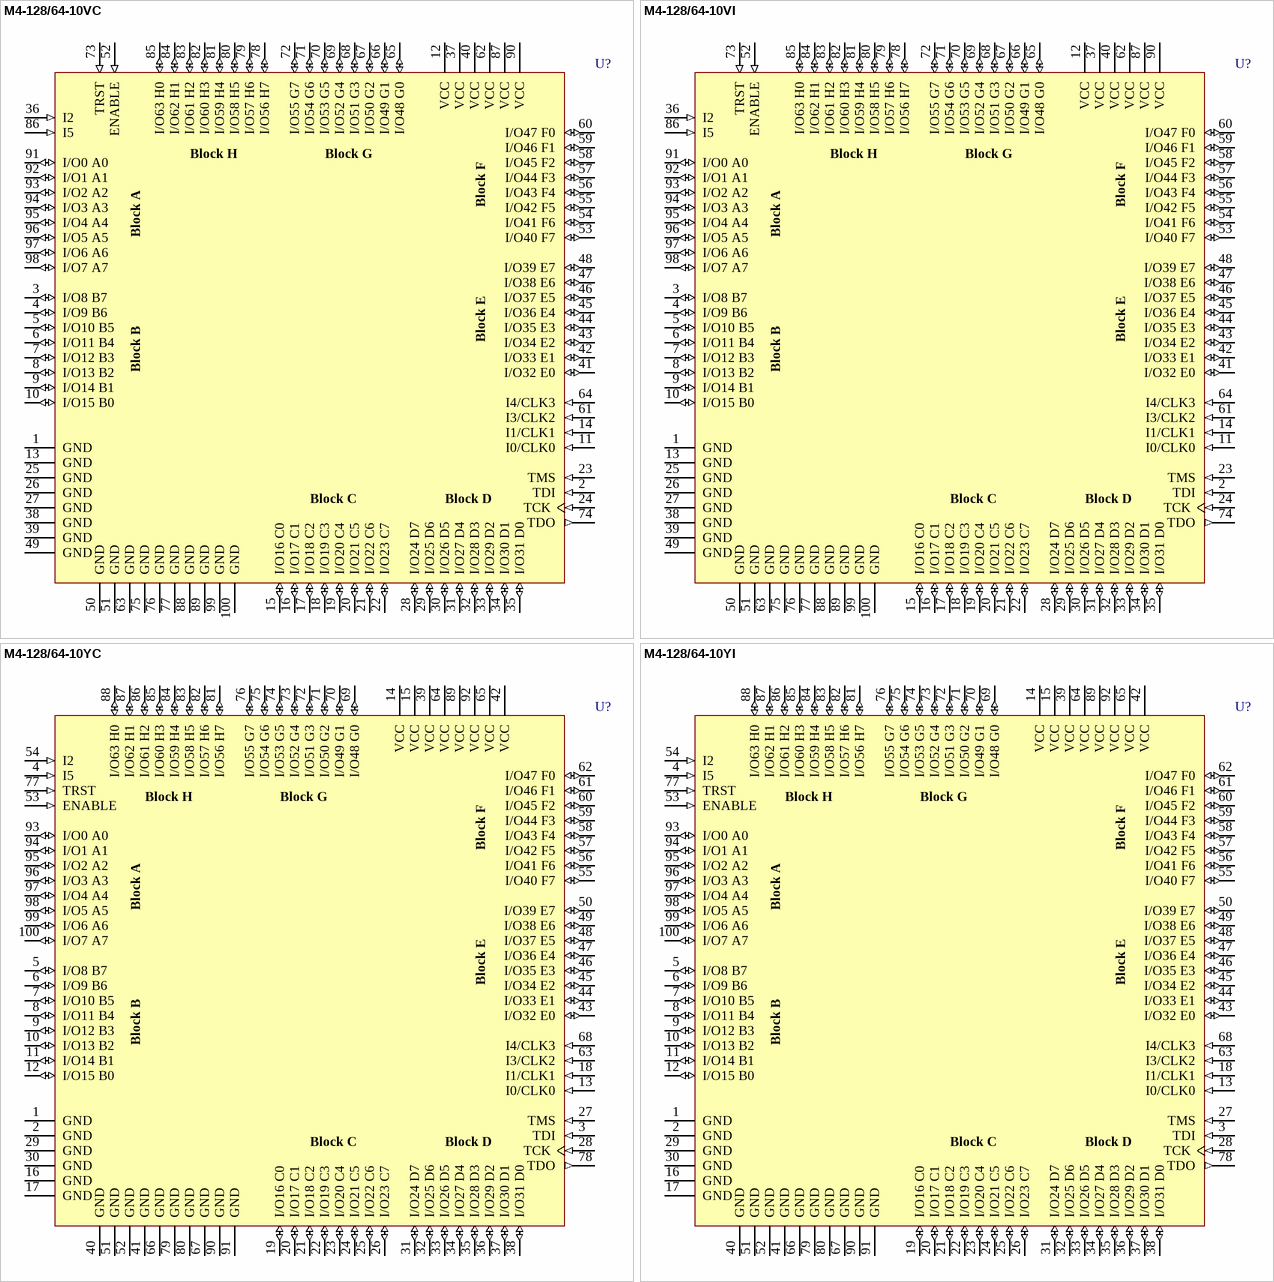
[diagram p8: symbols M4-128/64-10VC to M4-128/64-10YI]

## M4-128/64-10VC
designator U?
High-Performance EE CMOS In-System Programmable Logic
footprint TQFP100_N (Thin QFP, 100-Leads, Body 14x14mm, Pitch 0.5mm, IPC Medium Density)
footprint TQFP100_L (Thin QFP, 100-Leads, Body 14x14mm, Pitch 0.5mm, IPC High Density)
footprint TQFP100_M (Thin QFP, 100-Leads, Body 14x14mm, Pitch 0.5mm, IPC Low Density)
3D model M4-TQFP100 (100-Pin Thin Quad Flat Pack (TQFP100))
pins: 1 GND (power), 2 TDI (in), 3 I/O8 B7 (io), 4 I/O9 B6 (io), 5 I/O10 B5 (io), 6 I/O11 B4 (io), 7 I/O12 B3 (io), 8 I/O13 B2 (io), 9 I/O14 B1 (io), 10 I/O15 B0 (io), 11 I0/CLK0 (in), 12 VCC (power), 13 GND (power), 14 I1/CLK1 (in), 15 I/O16 C0 (io), 16 I/O17 C1 (io), 17 I/O18 C2 (io), 18 I/O19 C3 (io), 19 I/O20 C4 (io), 20 I/O21 C5 (io), 21 I/O22 C6 (io), 22 I/O23 C7 (io), 23 TMS (in), 24 TCK (in), 25 GND (power), 26 GND (power), 27 GND (power), 28 I/O24 D7 (io), 29 I/O25 D6 (io), 30 I/O26 D5 (io), 31 I/O27 D4 (io), 32 I/O28 D3 (io), 33 I/O29 D2 (io), 34 I/O30 D1 (io), 35 I/O31 D0 (io), 36 I2 (in), 37 VCC (power), 38 GND (power), 39 GND (power), 40 VCC (power), 41 I/O32 E0 (io), 42 I/O33 E1 (io), 43 I/O34 E2 (io), 44 I/O35 E3 (io), 45 I/O36 E4 (io), 46 I/O37 E5 (io), 47 I/O38 E6 (io), 48 I/O39 E7 (io), 49 GND (power), 50 GND (power), 51 GND (power), 52 ENABLE (in), 53 I/O40 F7 (io), 54 I/O41 F6 (io), 55 I/O42 F5 (io), 56 I/O43 F4 (io), 57 I/O44 F3 (io), 58 I/O45 F2 (io), 59 I/O46 F1 (io), 60 I/O47 F0 (io), 61 I3/CLK2 (in), 62 VCC (power), 63 GND (power), 64 I4/CLK3 (in), 65 I/O48 G0 (io), 66 I/O49 G1 (io), 67 I/O50 G2 (io), 68 I/O51 G3 (io), 69 I/O52 G4 (io), 70 I/O53 G5 (io), 71 I/O54 G6 (io), 72 I/O55 G7 (io), 73 TRST (in), 74 TDO (out), 75 GND (power), 76 GND (power), 77 GND (power), 78 I/O56 H7 (io), 79 I/O57 H6 (io), 80 I/O58 H5 (io), 81 I/O59 H4 (io), 82 I/O60 H3 (io), 83 I/O61 H2 (io), 84 I/O62 H1 (io), 85 I/O63 H0 (io), 86 I5 (in), 87 VCC (power), 88 GND (power), 89 GND (power), 90 VCC (power), 91 I/O0 A0 (io), 92 I/O1 A1 (io), 93 I/O2 A2 (io), 94 I/O3 A3 (io), 95 I/O4 A4 (io), 96 I/O5 A5 (io), 97 I/O6 A6 (io), 98 I/O7 A7 (io), 99 GND (power), 100 GND (power)

## M4-128/64-10VI
designator U?
High-Performance EE CMOS In-System Programmable Logic
footprint TQFP100_N (Thin QFP, 100-Leads, Body 14x14mm, Pitch 0.5mm, IPC Medium Density)
footprint TQFP100_L (Thin QFP, 100-Leads, Body 14x14mm, Pitch 0.5mm, IPC High Density)
footprint TQFP100_M (Thin QFP, 100-Leads, Body 14x14mm, Pitch 0.5mm, IPC Low Density)
3D model M4-TQFP100 (100-Pin Thin Quad Flat Pack (TQFP100))
pins: 1 GND (power), 2 TDI (in), 3 I/O8 B7 (io), 4 I/O9 B6 (io), 5 I/O10 B5 (io), 6 I/O11 B4 (io), 7 I/O12 B3 (io), 8 I/O13 B2 (io), 9 I/O14 B1 (io), 10 I/O15 B0 (io), 11 I0/CLK0 (in), 12 VCC (power), 13 GND (power), 14 I1/CLK1 (in), 15 I/O16 C0 (io), 16 I/O17 C1 (io), 17 I/O18 C2 (io), 18 I/O19 C3 (io), 19 I/O20 C4 (io), 20 I/O21 C5 (io), 21 I/O22 C6 (io), 22 I/O23 C7 (io), 23 TMS (in), 24 TCK (in), 25 GND (power), 26 GND (power), 27 GND (power), 28 I/O24 D7 (io), 29 I/O25 D6 (io), 30 I/O26 D5 (io), 31 I/O27 D4 (io), 32 I/O28 D3 (io), 33 I/O29 D2 (io), 34 I/O30 D1 (io), 35 I/O31 D0 (io), 36 I2 (in), 37 VCC (power), 38 GND (power), 39 GND (power), 40 VCC (power), 41 I/O32 E0 (io), 42 I/O33 E1 (io), 43 I/O34 E2 (io), 44 I/O35 E3 (io), 45 I/O36 E4 (io), 46 I/O37 E5 (io), 47 I/O38 E6 (io), 48 I/O39 E7 (io), 49 GND (power), 50 GND (power), 51 GND (power), 52 ENABLE (in), 53 I/O40 F7 (io), 54 I/O41 F6 (io), 55 I/O42 F5 (io), 56 I/O43 F4 (io), 57 I/O44 F3 (io), 58 I/O45 F2 (io), 59 I/O46 F1 (io), 60 I/O47 F0 (io), 61 I3/CLK2 (in), 62 VCC (power), 63 GND (power), 64 I4/CLK3 (in), 65 I/O48 G0 (io), 66 I/O49 G1 (io), 67 I/O50 G2 (io), 68 I/O51 G3 (io), 69 I/O52 G4 (io), 70 I/O53 G5 (io), 71 I/O54 G6 (io), 72 I/O55 G7 (io), 73 TRST (in), 74 TDO (out), 75 GND (power), 76 GND (power), 77 GND (power), 78 I/O56 H7 (io), 79 I/O57 H6 (io), 80 I/O58 H5 (io), 81 I/O59 H4 (io), 82 I/O60 H3 (io), 83 I/O61 H2 (io), 84 I/O62 H1 (io), 85 I/O63 H0 (io), 86 I5 (in), 87 VCC (power), 88 GND (power), 89 GND (power), 90 VCC (power), 91 I/O0 A0 (io), 92 I/O1 A1 (io), 93 I/O2 A2 (io), 94 I/O3 A3 (io), 95 I/O4 A4 (io), 96 I/O5 A5 (io), 97 I/O6 A6 (io), 98 I/O7 A7 (io), 99 GND (power), 100 GND (power)

## M4-128/64-10YC
designator U?
High-Performance EE CMOS In-System Programmable Logic
footprint PQFP100_N (QFP, 100-Leads, Body 20x14mm, Pitch 0.65mm, IPC Medium Density)
footprint PQFP100_L (QFP, 100-Leads, Body 20x14mm, Pitch 0.65mm, IPC High Density)
footprint PQFP100_M (QFP, 100-Leads, Body 20x14mm, Pitch 0.65mm, IPC Low Density)
3D model PQFP-100 (100-Pin Quad Flat Pack Rectangular 0.65 mm Pitch)
pins: 1 GND (power), 2 GND (power), 3 TDI (in), 4 I5 (in), 5 I/O8 B7 (io), 6 I/O9 B6 (io), 7 I/O10 B5 (io), 8 I/O11 B4 (io), 9 I/O12 B3 (io), 10 I/O13 B2 (io), 11 I/O14 B1 (io), 12 I/O15 B0 (io), 13 I0/CLK0 (in), 14 VCC (power), 15 VCC (power), 16 GND (power), 17 GND (power), 18 I1/CLK1 (in), 19 I/O16 C0 (io), 20 I/O17 C1 (io), 21 I/O18 C2 (io), 22 I/O19 C3 (io), 23 I/O20 C4 (io), 24 I/O21 C5 (io), 25 I/O22 C6 (io), 26 I/O23 C7 (io), 27 TMS (in), 28 TCK (in), 29 GND (power), 30 GND (power), 31 I/O24 D7 (io), 32 I/O25 D6 (io), 33 I/O26 D5 (io), 34 I/O27 D4 (io), 35 I/O28 D3 (io), 36 I/O29 D2 (io), 37 I/O30 D1 (io), 38 I/O31 D0 (io), 39 VCC (power), 40 GND (power), 41 GND (power), 42 VCC (power), 43 I/O32 E0 (io), 44 I/O33 E1 (io), 45 I/O34 E2 (io), 46 I/O35 E3 (io), 47 I/O36 E4 (io), 48 I/O37 E5 (io), 49 I/O38 E6 (io), 50 I/O39 E7 (io), 51 GND (power), 52 GND (power), 53 ENABLE (in), 54 I2 (in), 55 I/O40 F7 (io), 56 I/O41 F6 (io), 57 I/O42 F5 (io), 58 I/O43 F4 (io), 59 I/O44 F3 (io), 60 I/O45 F2 (io), 61 I/O46 F1 (io), 62 I/O47 F0 (io), 63 I3/CLK2 (in), 64 VCC (power), 65 VCC (power), 66 GND (power), 67 GND (power), 68 I4/CLK3 (in), 69 I/O48 G0 (io), 70 I/O49 G1 (io), 71 I/O50 G2 (io), 72 I/O51 G3 (io), 73 I/O52 G4 (io), 74 I/O53 G5 (io), 75 I/O54 G6 (io), 76 I/O55 G7 (io), 77 TRST (in), 78 TDO (out), 79 GND (power), 80 GND (power), 81 I/O56 H7 (io), 82 I/O57 H6 (io), 83 I/O58 H5 (io), 84 I/O59 H4 (io), 85 I/O60 H3 (io), 86 I/O61 H2 (io), 87 I/O62 H1 (io), 88 I/O63 H0 (io), 89 VCC (power), 90 GND (power), 91 GND (power), 92 VCC (power), 93 I/O0 A0 (io), 94 I/O1 A1 (io), 95 I/O2 A2 (io), 96 I/O3 A3 (io), 97 I/O4 A4 (io), 98 I/O5 A5 (io), 99 I/O6 A6 (io), 100 I/O7 A7 (io)

## M4-128/64-10YI
designator U?
High-Performance EE CMOS In-System Programmable Logic
footprint PQFP100_N (QFP, 100-Leads, Body 20x14mm, Pitch 0.65mm, IPC Medium Density)
footprint PQFP100_L (QFP, 100-Leads, Body 20x14mm, Pitch 0.65mm, IPC High Density)
footprint PQFP100_M (QFP, 100-Leads, Body 20x14mm, Pitch 0.65mm, IPC Low Density)
3D model PQFP-100 (100-Pin Quad Flat Pack Rectangular 0.65 mm Pitch)
pins: 1 GND (power), 2 GND (power), 3 TDI (in), 4 I5 (in), 5 I/O8 B7 (io), 6 I/O9 B6 (io), 7 I/O10 B5 (io), 8 I/O11 B4 (io), 9 I/O12 B3 (io), 10 I/O13 B2 (io), 11 I/O14 B1 (io), 12 I/O15 B0 (io), 13 I0/CLK0 (in), 14 VCC (power), 15 VCC (power), 16 GND (power), 17 GND (power), 18 I1/CLK1 (in), 19 I/O16 C0 (io), 20 I/O17 C1 (io), 21 I/O18 C2 (io), 22 I/O19 C3 (io), 23 I/O20 C4 (io), 24 I/O21 C5 (io), 25 I/O22 C6 (io), 26 I/O23 C7 (io), 27 TMS (in), 28 TCK (in), 29 GND (power), 30 GND (power), 31 I/O24 D7 (io), 32 I/O25 D6 (io), 33 I/O26 D5 (io), 34 I/O27 D4 (io), 35 I/O28 D3 (io), 36 I/O29 D2 (io), 37 I/O30 D1 (io), 38 I/O31 D0 (io), 39 VCC (power), 40 GND (power), 41 GND (power), 42 VCC (power), 43 I/O32 E0 (io), 44 I/O33 E1 (io), 45 I/O34 E2 (io), 46 I/O35 E3 (io), 47 I/O36 E4 (io), 48 I/O37 E5 (io), 49 I/O38 E6 (io), 50 I/O39 E7 (io), 51 GND (power), 52 GND (power), 53 ENABLE (in), 54 I2 (in), 55 I/O40 F7 (io), 56 I/O41 F6 (io), 57 I/O42 F5 (io), 58 I/O43 F4 (io), 59 I/O44 F3 (io), 60 I/O45 F2 (io), 61 I/O46 F1 (io), 62 I/O47 F0 (io), 63 I3/CLK2 (in), 64 VCC (power), 65 VCC (power), 66 GND (power), 67 GND (power), 68 I4/CLK3 (in), 69 I/O48 G0 (io), 70 I/O49 G1 (io), 71 I/O50 G2 (io), 72 I/O51 G3 (io), 73 I/O52 G4 (io), 74 I/O53 G5 (io), 75 I/O54 G6 (io), 76 I/O55 G7 (io), 77 TRST (in), 78 TDO (out), 79 GND (power), 80 GND (power), 81 I/O56 H7 (io), 82 I/O57 H6 (io), 83 I/O58 H5 (io), 84 I/O59 H4 (io), 85 I/O60 H3 (io), 86 I/O61 H2 (io), 87 I/O62 H1 (io), 88 I/O63 H0 (io), 89 VCC (power), 90 GND (power), 91 GND (power), 92 VCC (power), 93 I/O0 A0 (io), 94 I/O1 A1 (io), 95 I/O2 A2 (io), 96 I/O3 A3 (io), 97 I/O4 A4 (io), 98 I/O5 A5 (io), 99 I/O6 A6 (io), 100 I/O7 A7 (io)

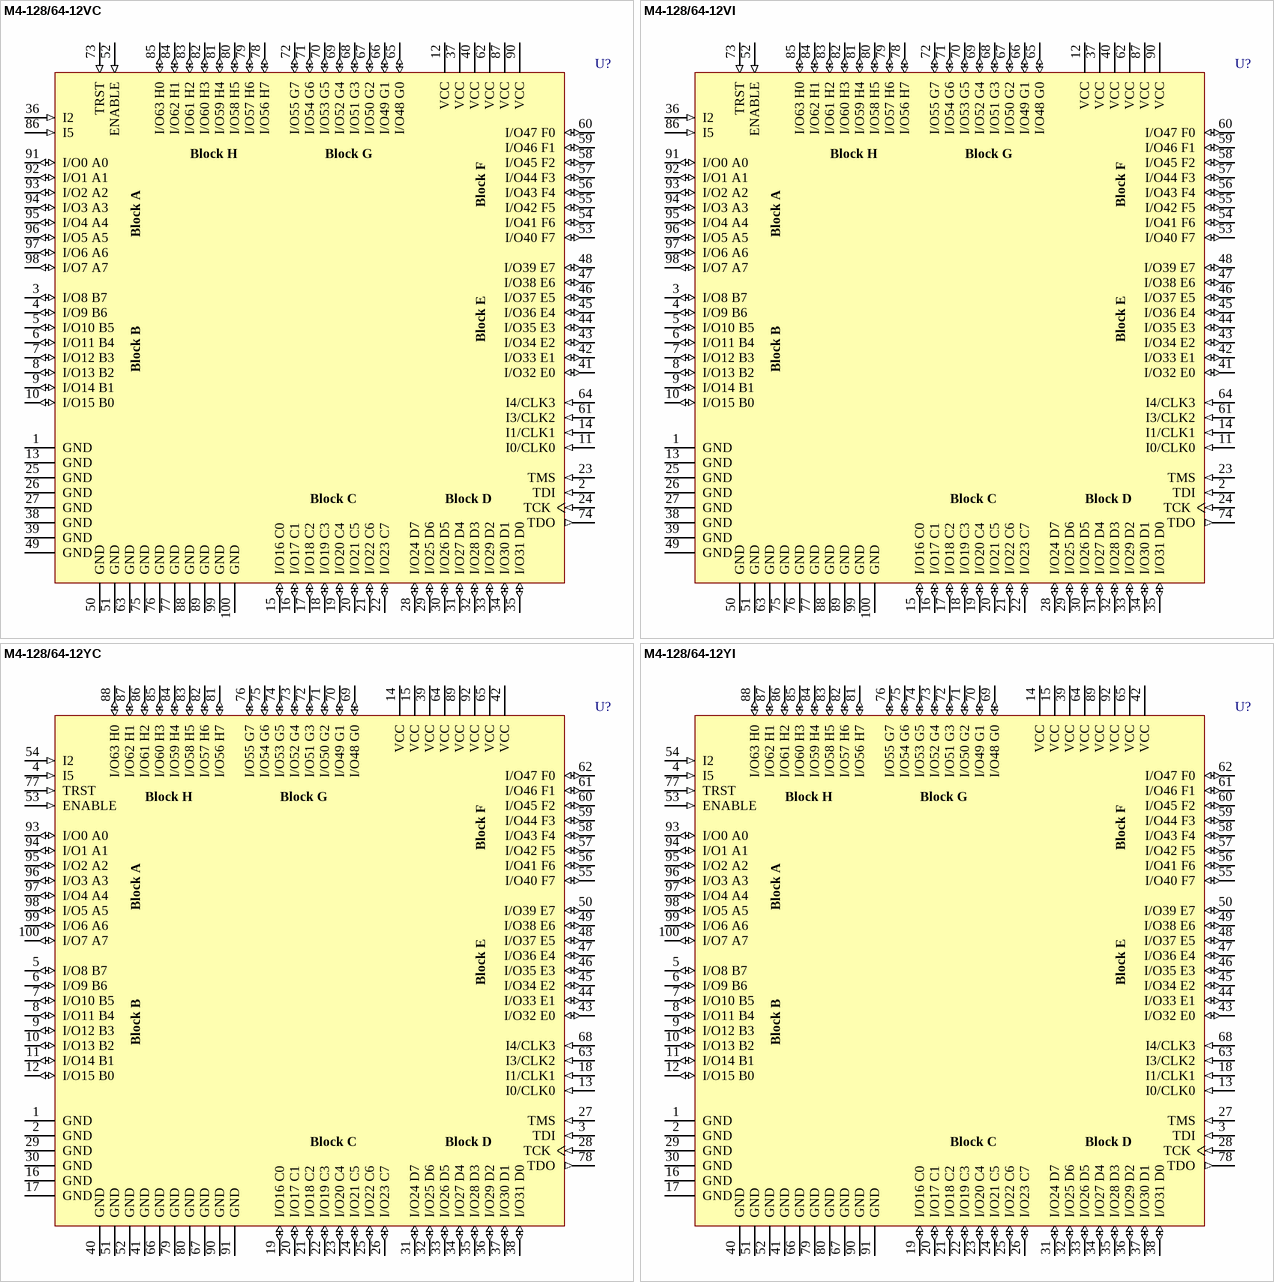
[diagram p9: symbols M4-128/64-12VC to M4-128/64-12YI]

## M4-128/64-12VC
designator U?
High-Performance EE CMOS In-System Programmable Logic
footprint TQFP100_N (Thin QFP, 100-Leads, Body 14x14mm, Pitch 0.5mm, IPC Medium Density)
footprint TQFP100_L (Thin QFP, 100-Leads, Body 14x14mm, Pitch 0.5mm, IPC High Density)
footprint TQFP100_M (Thin QFP, 100-Leads, Body 14x14mm, Pitch 0.5mm, IPC Low Density)
3D model M4-TQFP100 (100-Pin Thin Quad Flat Pack (TQFP100))
pins: 1 GND (power), 2 TDI (in), 3 I/O8 B7 (io), 4 I/O9 B6 (io), 5 I/O10 B5 (io), 6 I/O11 B4 (io), 7 I/O12 B3 (io), 8 I/O13 B2 (io), 9 I/O14 B1 (io), 10 I/O15 B0 (io), 11 I0/CLK0 (in), 12 VCC (power), 13 GND (power), 14 I1/CLK1 (in), 15 I/O16 C0 (io), 16 I/O17 C1 (io), 17 I/O18 C2 (io), 18 I/O19 C3 (io), 19 I/O20 C4 (io), 20 I/O21 C5 (io), 21 I/O22 C6 (io), 22 I/O23 C7 (io), 23 TMS (in), 24 TCK (in), 25 GND (power), 26 GND (power), 27 GND (power), 28 I/O24 D7 (io), 29 I/O25 D6 (io), 30 I/O26 D5 (io), 31 I/O27 D4 (io), 32 I/O28 D3 (io), 33 I/O29 D2 (io), 34 I/O30 D1 (io), 35 I/O31 D0 (io), 36 I2 (in), 37 VCC (power), 38 GND (power), 39 GND (power), 40 VCC (power), 41 I/O32 E0 (io), 42 I/O33 E1 (io), 43 I/O34 E2 (io), 44 I/O35 E3 (io), 45 I/O36 E4 (io), 46 I/O37 E5 (io), 47 I/O38 E6 (io), 48 I/O39 E7 (io), 49 GND (power), 50 GND (power), 51 GND (power), 52 ENABLE (in), 53 I/O40 F7 (io), 54 I/O41 F6 (io), 55 I/O42 F5 (io), 56 I/O43 F4 (io), 57 I/O44 F3 (io), 58 I/O45 F2 (io), 59 I/O46 F1 (io), 60 I/O47 F0 (io), 61 I3/CLK2 (in), 62 VCC (power), 63 GND (power), 64 I4/CLK3 (in), 65 I/O48 G0 (io), 66 I/O49 G1 (io), 67 I/O50 G2 (io), 68 I/O51 G3 (io), 69 I/O52 G4 (io), 70 I/O53 G5 (io), 71 I/O54 G6 (io), 72 I/O55 G7 (io), 73 TRST (in), 74 TDO (out), 75 GND (power), 76 GND (power), 77 GND (power), 78 I/O56 H7 (io), 79 I/O57 H6 (io), 80 I/O58 H5 (io), 81 I/O59 H4 (io), 82 I/O60 H3 (io), 83 I/O61 H2 (io), 84 I/O62 H1 (io), 85 I/O63 H0 (io), 86 I5 (in), 87 VCC (power), 88 GND (power), 89 GND (power), 90 VCC (power), 91 I/O0 A0 (io), 92 I/O1 A1 (io), 93 I/O2 A2 (io), 94 I/O3 A3 (io), 95 I/O4 A4 (io), 96 I/O5 A5 (io), 97 I/O6 A6 (io), 98 I/O7 A7 (io), 99 GND (power), 100 GND (power)

## M4-128/64-12VI
designator U?
High-Performance EE CMOS In-System Programmable Logic
footprint TQFP100_N (Thin QFP, 100-Leads, Body 14x14mm, Pitch 0.5mm, IPC Medium Density)
footprint TQFP100_L (Thin QFP, 100-Leads, Body 14x14mm, Pitch 0.5mm, IPC High Density)
footprint TQFP100_M (Thin QFP, 100-Leads, Body 14x14mm, Pitch 0.5mm, IPC Low Density)
3D model M4-TQFP100 (100-Pin Thin Quad Flat Pack (TQFP100))
pins: 1 GND (power), 2 TDI (in), 3 I/O8 B7 (io), 4 I/O9 B6 (io), 5 I/O10 B5 (io), 6 I/O11 B4 (io), 7 I/O12 B3 (io), 8 I/O13 B2 (io), 9 I/O14 B1 (io), 10 I/O15 B0 (io), 11 I0/CLK0 (in), 12 VCC (power), 13 GND (power), 14 I1/CLK1 (in), 15 I/O16 C0 (io), 16 I/O17 C1 (io), 17 I/O18 C2 (io), 18 I/O19 C3 (io), 19 I/O20 C4 (io), 20 I/O21 C5 (io), 21 I/O22 C6 (io), 22 I/O23 C7 (io), 23 TMS (in), 24 TCK (in), 25 GND (power), 26 GND (power), 27 GND (power), 28 I/O24 D7 (io), 29 I/O25 D6 (io), 30 I/O26 D5 (io), 31 I/O27 D4 (io), 32 I/O28 D3 (io), 33 I/O29 D2 (io), 34 I/O30 D1 (io), 35 I/O31 D0 (io), 36 I2 (in), 37 VCC (power), 38 GND (power), 39 GND (power), 40 VCC (power), 41 I/O32 E0 (io), 42 I/O33 E1 (io), 43 I/O34 E2 (io), 44 I/O35 E3 (io), 45 I/O36 E4 (io), 46 I/O37 E5 (io), 47 I/O38 E6 (io), 48 I/O39 E7 (io), 49 GND (power), 50 GND (power), 51 GND (power), 52 ENABLE (in), 53 I/O40 F7 (io), 54 I/O41 F6 (io), 55 I/O42 F5 (io), 56 I/O43 F4 (io), 57 I/O44 F3 (io), 58 I/O45 F2 (io), 59 I/O46 F1 (io), 60 I/O47 F0 (io), 61 I3/CLK2 (in), 62 VCC (power), 63 GND (power), 64 I4/CLK3 (in), 65 I/O48 G0 (io), 66 I/O49 G1 (io), 67 I/O50 G2 (io), 68 I/O51 G3 (io), 69 I/O52 G4 (io), 70 I/O53 G5 (io), 71 I/O54 G6 (io), 72 I/O55 G7 (io), 73 TRST (in), 74 TDO (out), 75 GND (power), 76 GND (power), 77 GND (power), 78 I/O56 H7 (io), 79 I/O57 H6 (io), 80 I/O58 H5 (io), 81 I/O59 H4 (io), 82 I/O60 H3 (io), 83 I/O61 H2 (io), 84 I/O62 H1 (io), 85 I/O63 H0 (io), 86 I5 (in), 87 VCC (power), 88 GND (power), 89 GND (power), 90 VCC (power), 91 I/O0 A0 (io), 92 I/O1 A1 (io), 93 I/O2 A2 (io), 94 I/O3 A3 (io), 95 I/O4 A4 (io), 96 I/O5 A5 (io), 97 I/O6 A6 (io), 98 I/O7 A7 (io), 99 GND (power), 100 GND (power)

## M4-128/64-12YC
designator U?
High-Performance EE CMOS In-System Programmable Logic
footprint PQFP100_N (QFP, 100-Leads, Body 20x14mm, Pitch 0.65mm, IPC Medium Density)
footprint PQFP100_L (QFP, 100-Leads, Body 20x14mm, Pitch 0.65mm, IPC High Density)
footprint PQFP100_M (QFP, 100-Leads, Body 20x14mm, Pitch 0.65mm, IPC Low Density)
3D model PQFP-100 (100-Pin Quad Flat Pack Rectangular 0.65 mm Pitch)
pins: 1 GND (power), 2 GND (power), 3 TDI (in), 4 I5 (in), 5 I/O8 B7 (io), 6 I/O9 B6 (io), 7 I/O10 B5 (io), 8 I/O11 B4 (io), 9 I/O12 B3 (io), 10 I/O13 B2 (io), 11 I/O14 B1 (io), 12 I/O15 B0 (io), 13 I0/CLK0 (in), 14 VCC (power), 15 VCC (power), 16 GND (power), 17 GND (power), 18 I1/CLK1 (in), 19 I/O16 C0 (io), 20 I/O17 C1 (io), 21 I/O18 C2 (io), 22 I/O19 C3 (io), 23 I/O20 C4 (io), 24 I/O21 C5 (io), 25 I/O22 C6 (io), 26 I/O23 C7 (io), 27 TMS (in), 28 TCK (in), 29 GND (power), 30 GND (power), 31 I/O24 D7 (io), 32 I/O25 D6 (io), 33 I/O26 D5 (io), 34 I/O27 D4 (io), 35 I/O28 D3 (io), 36 I/O29 D2 (io), 37 I/O30 D1 (io), 38 I/O31 D0 (io), 39 VCC (power), 40 GND (power), 41 GND (power), 42 VCC (power), 43 I/O32 E0 (io), 44 I/O33 E1 (io), 45 I/O34 E2 (io), 46 I/O35 E3 (io), 47 I/O36 E4 (io), 48 I/O37 E5 (io), 49 I/O38 E6 (io), 50 I/O39 E7 (io), 51 GND (power), 52 GND (power), 53 ENABLE (in), 54 I2 (in), 55 I/O40 F7 (io), 56 I/O41 F6 (io), 57 I/O42 F5 (io), 58 I/O43 F4 (io), 59 I/O44 F3 (io), 60 I/O45 F2 (io), 61 I/O46 F1 (io), 62 I/O47 F0 (io), 63 I3/CLK2 (in), 64 VCC (power), 65 VCC (power), 66 GND (power), 67 GND (power), 68 I4/CLK3 (in), 69 I/O48 G0 (io), 70 I/O49 G1 (io), 71 I/O50 G2 (io), 72 I/O51 G3 (io), 73 I/O52 G4 (io), 74 I/O53 G5 (io), 75 I/O54 G6 (io), 76 I/O55 G7 (io), 77 TRST (in), 78 TDO (out), 79 GND (power), 80 GND (power), 81 I/O56 H7 (io), 82 I/O57 H6 (io), 83 I/O58 H5 (io), 84 I/O59 H4 (io), 85 I/O60 H3 (io), 86 I/O61 H2 (io), 87 I/O62 H1 (io), 88 I/O63 H0 (io), 89 VCC (power), 90 GND (power), 91 GND (power), 92 VCC (power), 93 I/O0 A0 (io), 94 I/O1 A1 (io), 95 I/O2 A2 (io), 96 I/O3 A3 (io), 97 I/O4 A4 (io), 98 I/O5 A5 (io), 99 I/O6 A6 (io), 100 I/O7 A7 (io)

## M4-128/64-12YI
designator U?
High-Performance EE CMOS In-System Programmable Logic
footprint PQFP100_N (QFP, 100-Leads, Body 20x14mm, Pitch 0.65mm, IPC Medium Density)
footprint PQFP100_L (QFP, 100-Leads, Body 20x14mm, Pitch 0.65mm, IPC High Density)
footprint PQFP100_M (QFP, 100-Leads, Body 20x14mm, Pitch 0.65mm, IPC Low Density)
3D model PQFP-100 (100-Pin Quad Flat Pack Rectangular 0.65 mm Pitch)
pins: 1 GND (power), 2 GND (power), 3 TDI (in), 4 I5 (in), 5 I/O8 B7 (io), 6 I/O9 B6 (io), 7 I/O10 B5 (io), 8 I/O11 B4 (io), 9 I/O12 B3 (io), 10 I/O13 B2 (io), 11 I/O14 B1 (io), 12 I/O15 B0 (io), 13 I0/CLK0 (in), 14 VCC (power), 15 VCC (power), 16 GND (power), 17 GND (power), 18 I1/CLK1 (in), 19 I/O16 C0 (io), 20 I/O17 C1 (io), 21 I/O18 C2 (io), 22 I/O19 C3 (io), 23 I/O20 C4 (io), 24 I/O21 C5 (io), 25 I/O22 C6 (io), 26 I/O23 C7 (io), 27 TMS (in), 28 TCK (in), 29 GND (power), 30 GND (power), 31 I/O24 D7 (io), 32 I/O25 D6 (io), 33 I/O26 D5 (io), 34 I/O27 D4 (io), 35 I/O28 D3 (io), 36 I/O29 D2 (io), 37 I/O30 D1 (io), 38 I/O31 D0 (io), 39 VCC (power), 40 GND (power), 41 GND (power), 42 VCC (power), 43 I/O32 E0 (io), 44 I/O33 E1 (io), 45 I/O34 E2 (io), 46 I/O35 E3 (io), 47 I/O36 E4 (io), 48 I/O37 E5 (io), 49 I/O38 E6 (io), 50 I/O39 E7 (io), 51 GND (power), 52 GND (power), 53 ENABLE (in), 54 I2 (in), 55 I/O40 F7 (io), 56 I/O41 F6 (io), 57 I/O42 F5 (io), 58 I/O43 F4 (io), 59 I/O44 F3 (io), 60 I/O45 F2 (io), 61 I/O46 F1 (io), 62 I/O47 F0 (io), 63 I3/CLK2 (in), 64 VCC (power), 65 VCC (power), 66 GND (power), 67 GND (power), 68 I4/CLK3 (in), 69 I/O48 G0 (io), 70 I/O49 G1 (io), 71 I/O50 G2 (io), 72 I/O51 G3 (io), 73 I/O52 G4 (io), 74 I/O53 G5 (io), 75 I/O54 G6 (io), 76 I/O55 G7 (io), 77 TRST (in), 78 TDO (out), 79 GND (power), 80 GND (power), 81 I/O56 H7 (io), 82 I/O57 H6 (io), 83 I/O58 H5 (io), 84 I/O59 H4 (io), 85 I/O60 H3 (io), 86 I/O61 H2 (io), 87 I/O62 H1 (io), 88 I/O63 H0 (io), 89 VCC (power), 90 GND (power), 91 GND (power), 92 VCC (power), 93 I/O0 A0 (io), 94 I/O1 A1 (io), 95 I/O2 A2 (io), 96 I/O3 A3 (io), 97 I/O4 A4 (io), 98 I/O5 A5 (io), 99 I/O6 A6 (io), 100 I/O7 A7 (io)

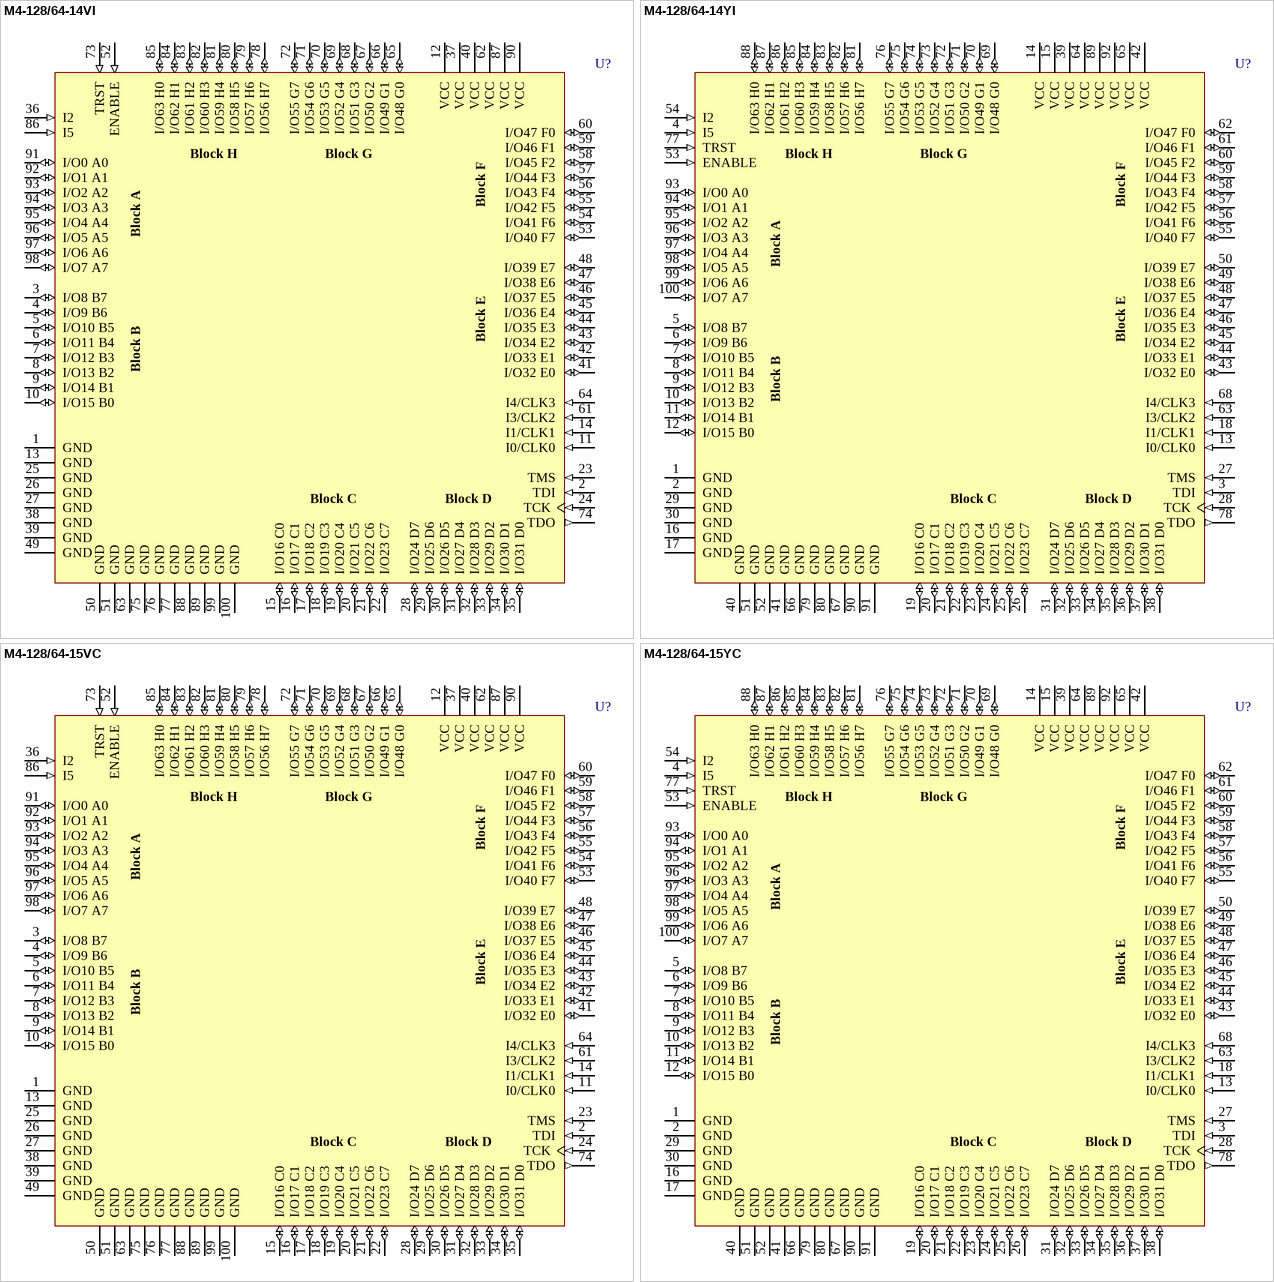
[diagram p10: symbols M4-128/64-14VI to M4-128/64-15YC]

## M4-128/64-14VI
designator U?
High-Performance EE CMOS In-System Programmable Logic
footprint TQFP100_N (Thin QFP, 100-Leads, Body 14x14mm, Pitch 0.5mm, IPC Medium Density)
footprint TQFP100_L (Thin QFP, 100-Leads, Body 14x14mm, Pitch 0.5mm, IPC High Density)
footprint TQFP100_M (Thin QFP, 100-Leads, Body 14x14mm, Pitch 0.5mm, IPC Low Density)
3D model M4-TQFP100 (100-Pin Thin Quad Flat Pack (TQFP100))
pins: 1 GND (power), 2 TDI (in), 3 I/O8 B7 (io), 4 I/O9 B6 (io), 5 I/O10 B5 (io), 6 I/O11 B4 (io), 7 I/O12 B3 (io), 8 I/O13 B2 (io), 9 I/O14 B1 (io), 10 I/O15 B0 (io), 11 I0/CLK0 (in), 12 VCC (power), 13 GND (power), 14 I1/CLK1 (in), 15 I/O16 C0 (io), 16 I/O17 C1 (io), 17 I/O18 C2 (io), 18 I/O19 C3 (io), 19 I/O20 C4 (io), 20 I/O21 C5 (io), 21 I/O22 C6 (io), 22 I/O23 C7 (io), 23 TMS (in), 24 TCK (in), 25 GND (power), 26 GND (power), 27 GND (power), 28 I/O24 D7 (io), 29 I/O25 D6 (io), 30 I/O26 D5 (io), 31 I/O27 D4 (io), 32 I/O28 D3 (io), 33 I/O29 D2 (io), 34 I/O30 D1 (io), 35 I/O31 D0 (io), 36 I2 (in), 37 VCC (power), 38 GND (power), 39 GND (power), 40 VCC (power), 41 I/O32 E0 (io), 42 I/O33 E1 (io), 43 I/O34 E2 (io), 44 I/O35 E3 (io), 45 I/O36 E4 (io), 46 I/O37 E5 (io), 47 I/O38 E6 (io), 48 I/O39 E7 (io), 49 GND (power), 50 GND (power), 51 GND (power), 52 ENABLE (in), 53 I/O40 F7 (io), 54 I/O41 F6 (io), 55 I/O42 F5 (io), 56 I/O43 F4 (io), 57 I/O44 F3 (io), 58 I/O45 F2 (io), 59 I/O46 F1 (io), 60 I/O47 F0 (io), 61 I3/CLK2 (in), 62 VCC (power), 63 GND (power), 64 I4/CLK3 (in), 65 I/O48 G0 (io), 66 I/O49 G1 (io), 67 I/O50 G2 (io), 68 I/O51 G3 (io), 69 I/O52 G4 (io), 70 I/O53 G5 (io), 71 I/O54 G6 (io), 72 I/O55 G7 (io), 73 TRST (in), 74 TDO (out), 75 GND (power), 76 GND (power), 77 GND (power), 78 I/O56 H7 (io), 79 I/O57 H6 (io), 80 I/O58 H5 (io), 81 I/O59 H4 (io), 82 I/O60 H3 (io), 83 I/O61 H2 (io), 84 I/O62 H1 (io), 85 I/O63 H0 (io), 86 I5 (in), 87 VCC (power), 88 GND (power), 89 GND (power), 90 VCC (power), 91 I/O0 A0 (io), 92 I/O1 A1 (io), 93 I/O2 A2 (io), 94 I/O3 A3 (io), 95 I/O4 A4 (io), 96 I/O5 A5 (io), 97 I/O6 A6 (io), 98 I/O7 A7 (io), 99 GND (power), 100 GND (power)

## M4-128/64-14YI
designator U?
High-Performance EE CMOS In-System Programmable Logic
footprint PQFP100_N (QFP, 100-Leads, Body 20x14mm, Pitch 0.65mm, IPC Medium Density)
footprint PQFP100_L (QFP, 100-Leads, Body 20x14mm, Pitch 0.65mm, IPC High Density)
footprint PQFP100_M (QFP, 100-Leads, Body 20x14mm, Pitch 0.65mm, IPC Low Density)
3D model PQFP-100 (100-Pin Quad Flat Pack Rectangular 0.65 mm Pitch)
pins: 1 GND (power), 2 GND (power), 3 TDI (in), 4 I5 (in), 5 I/O8 B7 (io), 6 I/O9 B6 (io), 7 I/O10 B5 (io), 8 I/O11 B4 (io), 9 I/O12 B3 (io), 10 I/O13 B2 (io), 11 I/O14 B1 (io), 12 I/O15 B0 (io), 13 I0/CLK0 (in), 14 VCC (power), 15 VCC (power), 16 GND (power), 17 GND (power), 18 I1/CLK1 (in), 19 I/O16 C0 (io), 20 I/O17 C1 (io), 21 I/O18 C2 (io), 22 I/O19 C3 (io), 23 I/O20 C4 (io), 24 I/O21 C5 (io), 25 I/O22 C6 (io), 26 I/O23 C7 (io), 27 TMS (in), 28 TCK (in), 29 GND (power), 30 GND (power), 31 I/O24 D7 (io), 32 I/O25 D6 (io), 33 I/O26 D5 (io), 34 I/O27 D4 (io), 35 I/O28 D3 (io), 36 I/O29 D2 (io), 37 I/O30 D1 (io), 38 I/O31 D0 (io), 39 VCC (power), 40 GND (power), 41 GND (power), 42 VCC (power), 43 I/O32 E0 (io), 44 I/O33 E1 (io), 45 I/O34 E2 (io), 46 I/O35 E3 (io), 47 I/O36 E4 (io), 48 I/O37 E5 (io), 49 I/O38 E6 (io), 50 I/O39 E7 (io), 51 GND (power), 52 GND (power), 53 ENABLE (in), 54 I2 (in), 55 I/O40 F7 (io), 56 I/O41 F6 (io), 57 I/O42 F5 (io), 58 I/O43 F4 (io), 59 I/O44 F3 (io), 60 I/O45 F2 (io), 61 I/O46 F1 (io), 62 I/O47 F0 (io), 63 I3/CLK2 (in), 64 VCC (power), 65 VCC (power), 66 GND (power), 67 GND (power), 68 I4/CLK3 (in), 69 I/O48 G0 (io), 70 I/O49 G1 (io), 71 I/O50 G2 (io), 72 I/O51 G3 (io), 73 I/O52 G4 (io), 74 I/O53 G5 (io), 75 I/O54 G6 (io), 76 I/O55 G7 (io), 77 TRST (in), 78 TDO (out), 79 GND (power), 80 GND (power), 81 I/O56 H7 (io), 82 I/O57 H6 (io), 83 I/O58 H5 (io), 84 I/O59 H4 (io), 85 I/O60 H3 (io), 86 I/O61 H2 (io), 87 I/O62 H1 (io), 88 I/O63 H0 (io), 89 VCC (power), 90 GND (power), 91 GND (power), 92 VCC (power), 93 I/O0 A0 (io), 94 I/O1 A1 (io), 95 I/O2 A2 (io), 96 I/O3 A3 (io), 97 I/O4 A4 (io), 98 I/O5 A5 (io), 99 I/O6 A6 (io), 100 I/O7 A7 (io)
